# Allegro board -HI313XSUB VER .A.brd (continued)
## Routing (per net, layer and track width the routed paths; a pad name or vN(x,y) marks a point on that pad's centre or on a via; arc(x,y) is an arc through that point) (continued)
3V3_MOS_T: length 14.3
  TOP w0.381: U18.3 40.74,37.74
  TOP w0.508: LB16.1 v1(49,42.51) ; v1(15.79,39.06) 15.79,39.64 15.91,39.77 R221.1
  BOTTOM w0.508: v1(40.3,41.5) 41.31,42.51 v1(49,42.51)
  vias: v1(12.82,29.38) v1(12.84,28.62) v1(40.25,26.82) v1(40.3,35.91) v1(40.3,35.15) v1(40.27,26.05)
3V3_RF: length 37.8
  TOP w0.203: 149.13,63.72 149.13,65.42 148.82,65.73 U34.23 ; U34.28 148.94,67.73
  TOP w0.254: 148.94,67.73 149.19,67.73 150.14,68.67 C169.2
  TOP w0.381: 152.81,62.17 152.66,62.32 150.52,62.32 150.12,62.73 C144.1 149.76,63.09 149.13,63.72 ; C169.2 150.2,68.05 150.4,67.86 152.45,67.86 ; 164.78,59.05 165.62,59.89 R112.2
  TOP w0.508: 152.45,67.86 153.01,67.3 153.01,62.38 152.81,62.17
  TOP w0.635: C296.1 156.98,50.74 C57.1 C195.2 153.17,52.67 154.33,53.84 154.33,59.1 152.81,60.63 152.81,62.17
3V3_TUNER: length 88
  TOP w0.254: U20.11 24.84,59.92 23.43,58.51 ; 31.98,62.39 31.34,62.39 31,62.05 C280.2 30.65,61.69 29.88,60.92 U20.22 ; U20.15 26.97,58.01 25.82,56.86 C291.1 25.34,56.64 25.16,56.46 25.16,55.59
  TOP w0.381: 23.43,58.51 23,58.51 C286.1 22.54,58.41 22.14,58.01 22.14,54.96 22.52,54.58 25.06,54.58 25.16,54.48 ; 25.16,54.48 25.54,54.1 R213.1 26.72,52.56 27.27,52.01 v1(27.27,51.36) R225.1 ; 25.16,54.48 25.16,55.59 ; C260.1 42.57,52.78 42.84,53.05 42.84,68.8 40.93,70.71 37.63,70.71 32.78,65.86 32.78,63.06 32.11,62.39 31.98,62.39
  TOP w0.508: v1(33.05,51.99) 34.77,50.26 40.93,50.26 41.62,50.95 C260.1 C259.1 43.96,50.95 46.27,48.63 C328.1 46.27,46.08 47.3,45.05 LB16.2 ; R211.1 v1(29.25,51.98)
  BOTTOM w0.508: v1(33.05,51.99) 32.38,51.99 32.38,51.98 v1(29.25,51.98) 27.88,51.98 v1(27.27,51.36)
5V0_MOS_S:
  vias: v1(140.93,12.03) v1(140.95,12.82) v1(165.34,63.47) v1(165.34,62.71)
5V0_MOS_T: length 97.3
  TOP w0.508: Q12.2 v1(48.93,60.04)
  TOP w0.762: Q12.2 48.73,63.42 R200.1 ; v1(11.24,30.82) v1(11.24,29.99) 11.62,29.61 C352.1 11.62,26.38 14.21,23.79 49.75,23.79 52.76,26.8 52.76,29.32 52.77,29.33 v1(52.77,60.04)
  BOTTOM w0.508: v1(48.93,60.04) C301.1 v1(52.77,60.04)
  BOTTOM w0.762: v1(11.24,29.99) v1(11.24,30.82) 11.24,34.07 10.54,34.77 J4.3
12V0_MOS_S: length 11.5
  TOP w0.152: R121.1 164.81,19.61
  TOP w0.381: v1(164.81,20.39) 164.81,19.61 164.8,19.61 R117.1
  BOTTOM w0.381: v1(157.06,15.76) 159.61,15.76 164.24,20.39 v1(164.81,20.39)
GND: length 688.5
  TOP w0.152: M1.5 M4.1 ; M5.5 M3.1
  TOP w0.203: U5.9 93.53,37.07 v1(93.75,36.86) 93.56,36.67 U5.8 ; v1(92.44,39.15) 92.08,38.79 U5.11 ; 139.77,39.35 139.77,39.35 U2.34 ; v1(89.9,39.76) 90.08,39.58 U5.16 ; 22.14,39.36 22.13,39.37 U25.34 ; v1(93.65,35.71) 93.5,35.87 U5.6 ; U2.47 139.37,35.64 v1(139.9,36.17) ; 141.81,39.35 141.77,39.38 U2.29 ; v1(89.14,38.99) 89.28,38.85 U5.18 ; v1(93.71,37.62) 93.26,37.62 93.11,37.47 U5.10 ; U25.29 24.13,39.05
  TOP w0.254: U4.5 87.77,64.56 ; D3.1 v1(95.31,67.08) ; C290.2 25.82,57.63 26.47,58.27 U20.14 26.47,59.52 ; 86.6,61.64 86.42,61.64 86.01,61.24 U4.16 ; U4.18 86.77,61.58 ; 89.47,64.41 89.47,64.66 89.77,64.97 U4.1 90.29,65.49 v1(90.36,65.55) ; U4.22 88.77,61.48 ; C18.2 v1(91.42,42.07) ; U4.29 89.6,63.24 ; 86.51,63.74 U4.11
  TOP w0.305: C16.2 89.77,30.08 v1(89.63,29.94) ; C72.2 v1(84.49,40.95) ; v1(86.47,58.57) 86.47,58.34 86.77,58.03 C82.2 ; C21.2 v1(84.56,35.84) ; C26.2 89.9,42.02 v1(89.85,42.07) ; C23.2 84.69,36.86 v1(84.56,36.73) ; C17.2 94.34,36 94.05,35.71 v1(93.65,35.71) ; C32.2 v1(95.69,36.18) ; C53.2 v1(90.91,29.98)
  TOP w0.356: v1(91.38,62.07) 91.68,61.77 91.68,60.83 v1(91.78,60.72)
  TOP w0.381: C311.2 18.15,40.18 v1(18.5,39.82) ; 120.32,24.99 J5.4 ; J5.4 121.51,26.18 ; J5.4 121.51,23.79 ; J5.4 122.71,24.99 ; J7.2 63.96,33.42 ; J7.2 65.15,32.23 ; J7.2 63.96,31.03 ; J7.2 62.76,32.23 ; 23.4,80.05 J2.4 ; J2.4 26.37,81.37 ; J2.4 23.4,82.69 ; J2.4 20.43,81.37 ; J4.20 7.71,55.09 ; J4.20 6.52,56.28 ; J4.20 5.32,55.09 ; J4.20 6.52,53.89 ; J3.20 121.39,56.28 ; J3.20 120.2,55.09 ; J3.20 121.39,53.89 ; J3.20 122.59,55.09 ; C287.2 147.57,80.64 147.57,81.17 ; C287.2 147.58,81.17 ; C287.2 148.1,80.64 ; 148.73,72.4 C305.1 149.8,72.4 ; C304.1 146.76,75.15 146.76,75.68 ; C304.1 146.75,75.68 ; C304.1 146.22,75.15 ; 5.32,34.77 J4.4 ; J4.4 6.52,35.96 ; J4.4 7.71,34.77 ; J4.4 6.52,33.57 ; 144.42,79.22 C166.2 ; 144.42,79.22 144.95,79.22 ; 144.42,79.22 144.42,78.68 ; C166.2 144.42,79.75 ; C166.2 144.95,79.25 ; C286.2 v1(23.71,57.6) ; C156.2 30.19,28.57 ; C156.2 27.55,28.57 ; C156.2 28.87,27.53 ; 121.51,21.25 J5.2 ; J5.2 122.71,22.45 ; J5.2 120.32,22.45 ; J5.2 121.51,23.64 ; J16.4 139.55,81.39 ; J16.4 133.61,81.39 ; J16.4 136.58,80.07 ; J16.4 136.58,82.71 ; 64.09,23.79 J6.4 ; J6.4 62.9,24.99 ; J6.4 64.09,26.18 ; J6.4 65.28,24.99 ; 98.86,57.27 J1.7 ; J1.7 100.19,55.18 ; J1.7 100.19,59.35 ; J1.7 101.51,57.27 ; 5.32,39.85 J4.8 ; J4.8 6.52,38.65 ; J4.8 7.71,39.85 ; J4.8 6.52,41.04 ; 122.86,22.45 J5.1 ; J5.1 124.05,21.25 ; J5.1 124.05,23.64 ; J1.8 101.51,75.77 ; J1.8 98.97,75.77 ; J1.8 100.19,77.85 ; J1.8 100.19,73.68 ; J16.7 159.07,57.27 ; J16.7 157.75,55.18 ; J16.7 157.75,59.35 ; J16.7 156.43,57.27 ; 65.44,24.99 J6.3 ; J6.3 67.82,24.99 ; J6.3 66.63,26.18 ; J6.3 66.63,23.79 ; J1.6 74.16,57.27 ; J1.6 72.84,59.35 ; J1.6 71.51,57.27 ; J1.6 72.84,55.18 ; J4.18 7.71,52.55 ; J4.18 5.32,52.55 ; J4.18 6.52,51.35 ; J4.18 6.52,53.74 ; J6.2 64.09,23.64 ; J6.2 64.09,21.25 ; J6.2 65.28,22.45 ; J6.2 62.9,22.45 ; 145.21,73.27 C148.2 ; C148.2 144.15,73.27 ; C148.2 144.68,73.81 ; 7.86,39.85 J4.7 ; J4.7 9.06,38.65 ; J4.7 9.06,41.04 ; J1.4 79.01,82.71 ; J1.4 81.98,81.39 ; J1.4 79.01,80.07 ; J1.4 76.04,81.39 ; 157.75,73.68 J16.8 157.75,77.85 ; v1(16.52,39.31) 16.78,39.31 R209.2 ; 63.96,33.57 J7.4 ; J7.4 63.96,35.96 ; J7.4 62.76,34.77 ; J7.4 65.15,34.77 ; 154.38,70.45 C78.2 ; 62.76,55.09 J7.20 ; J7.20 63.96,56.28 ; J7.20 65.15,55.09 ; J7.20 63.96,53.89 ; 44.58,73.67 J2.8 ; J2.8 43.25,75.75 ; J2.8 45.9,75.75 ; J2.8 44.58,77.84 ; 63.96,36.11 J7.6 ; J7.6 63.96,38.5 ; J7.6 62.76,37.31 ; J7.6 65.15,37.31 ; J2.3 41.37,81.37 ; J2.3 35.43,81.37 ; J2.3 38.4,82.69 ; 62.76,52.55 J7.18 ; J7.18 63.96,51.35 ; J7.18 65.15,52.55 ; J7.18 63.96,53.74 ; C298.2 v1(16.55,34.94) ; C295.2 16.35,37.53 v1(16.09,37.79) ; 161.74,16.22 R102.1 ; J16.3 151.58,82.71 ; J16.3 148.61,81.39 ; J16.3 154.55,81.39 ; 7.99,22.45 J15.1 ; J15.1 9.18,23.64 ; J15.1 10.38,22.45 ; J15.1 9.18,21.25 ; v1(133.94,36.26) 134.43,35.78 C176.2 ; C545.2 v1(140.46,69.31) ; J15.4 6.64,26.18 ; J15.4 5.45,24.99 ; J15.4 6.64,23.79 ; J15.4 7.84,24.99 ; 155.67,67.51 C104.2 155.14,68.04 ; 6.64,21.25 J15.2 ; J15.2 7.84,22.45 ; J15.2 5.45,22.45 ; J15.2 6.64,23.64 ; 146.43,81.17 C288.2 145.89,80.64 ; R4.2 147.1,33.65 v1(146.95,33.5) ; 148.49,71.27 148.49,70.73 C130.2 ; C328.2 48.81,49.51 ; C328.2 47.68,48.19 ; C328.2 48.81,46.87 ; 7.99,24.99 J15.3 ; J15.3 9.18,26.18 ; J15.3 10.38,24.99 ; J15.3 9.18,23.79 ; C174.2 v1(148.9,38.5) ; 124.05,23.79 J5.3 122.86,24.99 ; C217.2 134.17,40.81 v1(133.89,40.53) ; C136.2 v1(157.87,14.59) ; J6.1 67.82,22.45 ; J6.1 65.44,22.45 ; J6.1 66.63,21.25 ; J6.1 66.63,23.64 ; J4.6 6.52,38.5 ; J4.6 5.32,37.31 ; J4.6 7.71,37.31 ; J4.6 6.52,36.11 ; C33.2 v1(85.15,68.04) ; J2.6 17.23,59.34 ; J2.6 18.55,57.25 ; J2.6 17.23,55.17 ; C535.2 v1(141.1,66.26) C241.2 ; L16.1 139.59,73.44 ; L16.1 139.05,72.92 ; L16.1 140.12,72.92 ; 130.4,73.68 J16.5 ; J16.5 130.4,77.85 ; J16.5 131.72,75.77 ; J16.5 129.08,75.77 ; v1(20.11,42.13) 19.42,42.13 R208.2 ; v1(32.55,61.89) 32.35,61.69 C280.1 ; v1(146.97,36.98) 147.13,36.82 C38.2 R83.2 ; 65.3,39.85 J7.7 66.5,38.65 ; C172.2 v1(149,41.17) ; C221.2 v1(133.94,38.75) ; J2.5 17.23,77.84 ; J2.5 17.23,73.67 ; J2.5 15.9,75.75 ; J2.5 18.55,75.75 ; v1(91.78,60.72) 91.78,60.56 92.2,60.14 v1(92.3,60.14) 92.57,60.14 92.66,60.05 93.57,60.05 v1(93.66,59.96) ; J4.2 6.52,33.42 ; J4.2 6.52,31.03 ; J4.2 7.71,32.23 ; J4.2 5.32,32.23 ; 155.14,66.51 C58.2 ; C58.2 155.67,65.98 ; C58.2 155.67,67.05 ; C226.2 v1(147.07,42.49) ; J3.18 122.59,52.55 ; J3.18 121.39,53.74 ; J3.18 120.2,52.55 ; J3.18 121.39,51.35 ; v1(133.94,42.21) 134.35,42.21 R41.2 ; J7.8 65.15,39.85 ; J7.8 63.96,38.65 ; J7.8 62.76,39.85 ; J7.8 63.96,41.04 ; C5.2 v1(85.22,67.08) ; J1.5 72.84,77.85 ; J1.5 74.16,75.77 ; J1.5 72.84,73.68 ; J1.5 71.51,75.77 ; C291.2 v1(25.82,55.09) ; J2.7 45.9,57.25 ; J2.7 44.58,55.17 ; J2.7 44.58,59.34 ; 94.01,80.07 J1.3 ; J1.3 96.98,81.39 ; J1.3 91.04,81.39 ; J1.3 94.01,82.71 ; C163.1 v1(158.94,14.62) ; C293.1 v1(24.52,63.6) ; v1(152.49,68.67) C169.1 151.6,69.36 ; 149.02,70.73 C130.2 ; C130.2 148.5,71.27 ; C534.2 v1(140.46,60.29) ; C22.2 94.6,31.95 ; C538.2 v1(140.46,61.56) ; v1(152.32,67.02) C487.1 ; C536.2 v1(140.46,68.29) ; 129.08,57.27 J16.6 130.4,59.35 ; C253.2 v1(26.73,55.85) ; C537.2 v1(140.46,64.1) ; R64.2 v1(138.2,62.83) ; C34.2 v1(106.77,34.59) ; C414.2 144.68,71.82 ; C284.1 v1(30.52,59.89) ; R59.2 v1(140.46,62.83)
  TOP w0.508: R1.2 v1(104.44,34.03) ; C71.1 v1(78.4,35.83)
  TOP w0.533: 104.78,49.09 C60.2 ; C60.2 105.83,50.34 ; C60.2 106.89,49.09 ; C60.2 105.83,47.85 ; C296.2 158.17,48.06 ; C296.2 159.42,47.01 ; C296.2 158.17,45.95 ; C296.2 156.93,47.01 ; 146.46,21.67 C134.2 ; C134.2 146.46,23.78 ; C134.2 147.71,22.73 ; C134.2 145.22,22.73 ; C4.2 109.49,30.32 ; C4.2 108.52,31.57 ; C4.2 108.52,29.08 ; 131.65,57.27 J16.6 130.4,55.26
  BOTTOM w0.152: 12.61,26.05 12.41,26.05 12.33,25.98
  BOTTOM w0.381: 65.44,24.99 J6.3 ; J6.3 66.63,23.79 ; J6.3 67.82,24.99 ; J6.3 66.63,26.18 ; J6.2 65.28,22.45 ; J6.2 62.9,22.45 ; J6.2 64.09,21.25 ; J6.2 64.09,23.64 ; 121.39,51.35 J3.18 ; J3.18 121.39,53.74 ; J3.18 120.2,52.55 ; J3.18 122.59,52.55 ; J5.3 124.05,26.18 ; J5.3 124.05,23.79 ; J5.3 122.86,24.99 ; J5.3 125.25,24.99 ; J7.7 66.5,41.04 ; J7.7 65.3,39.85 ; J7.7 66.5,38.65 ; J7.7 67.69,39.85 ; 62.76,39.85 J7.8 ; J7.8 63.96,38.65 ; J7.8 63.96,41.04 ; J7.8 65.15,39.85 ; J5.4 122.71,24.99 ; J5.4 121.51,26.18 ; J5.4 121.51,23.79 ; J5.4 120.32,24.99 ; 6.52,53.89 J4.20 ; J4.20 7.71,55.09 ; J4.20 6.52,56.28 ; J4.20 5.32,55.09 ; J6.4 65.28,24.99 ; J6.4 62.9,24.99 ; J6.4 64.09,23.79 ; J6.4 64.09,26.18 ; 38.4,80.05 J2.3 ; J2.3 38.4,82.69 ; J2.3 35.43,81.37 ; J2.3 41.37,81.37 ; J15.2 6.64,23.64 ; J15.2 6.64,21.25 ; J15.2 5.45,22.45 ; J15.2 7.84,22.45 ; 120.2,34.77 J3.4 ; J3.4 122.59,34.77 ; J3.4 121.39,33.57 ; J3.4 121.39,35.96 ; 63.96,33.57 J7.4 ; J7.4 63.96,35.96 ; J7.4 62.76,34.77 ; J7.4 65.15,34.77 ; 9.06,38.65 J4.7 ; J4.7 7.86,39.85 ; J4.7 10.25,39.85 ; J4.7 9.06,41.04 ; C328.2 48.81,49.51 ; C328.2 49.94,48.19 ; C328.2 47.68,48.19 ; C328.2 48.81,46.87 ; 121.39,36.11 J3.6 ; J3.6 121.39,38.5 ; J3.6 120.2,37.31 ; J3.6 122.59,37.31 ; 5.32,32.23 J4.2 ; J4.2 7.71,32.23 ; J4.2 6.52,33.42 ; J4.2 6.52,31.03 ; J2.4 26.37,81.37 ; J2.4 23.4,82.69 ; J2.4 23.4,80.05 ; J2.4 20.43,81.37 ; J16.4 136.58,82.71 ; J16.4 133.61,81.39 ; J16.4 139.55,81.39 ; J16.4 136.58,80.07 ; J1.4 81.98,81.39 ; J1.4 79.01,80.07 ; J1.4 76.04,81.39 ; J1.4 79.01,82.71 ; J2.8 45.9,75.75 ; J2.8 44.58,73.67 ; J2.8 43.25,75.75 ; J2.8 44.58,77.84 ; 120.2,55.09 J3.20 ; J3.20 121.39,53.89 ; J3.20 122.59,55.09 ; J3.20 121.39,56.28 ; 121.39,38.65 J3.8 ; J3.8 120.2,39.85 ; J3.8 121.39,41.04 ; J3.8 122.59,39.85 ; J2.6 17.23,59.34 ; J2.6 18.55,57.25 ; J2.6 15.9,57.25 ; J2.6 17.23,55.17 ; 123.93,38.65 J3.7 ; J3.7 123.93,41.04 ; J3.7 125.13,39.85 ; J3.7 122.74,39.85 ; v1(30.52,59.89) 29.92,59.89 29.82,59.78 v1(28.11,59.78) ; J16.3 154.55,81.39 ; J16.3 151.58,82.71 ; J16.3 148.61,81.39 ; J16.3 151.58,80.07 ; 6.52,36.11 J4.6 ; J4.6 6.52,38.5 ; J4.6 5.32,37.31 ; J4.6 7.71,37.31 ; J7.2 65.15,32.23 ; J7.2 63.96,31.03 ; J7.2 62.76,32.23 ; J7.2 63.96,33.42 ; J5.1 125.25,22.45 ; J5.1 122.86,22.45 ; J5.1 124.05,21.25 ; J5.1 124.05,23.64 ; J15.4 7.84,24.99 ; J15.4 5.45,24.99 ; J15.4 6.64,26.18 ; J15.4 6.64,23.79 ; J6.1 67.82,22.45 ; J6.1 65.44,22.45 ; J6.1 66.63,21.25 ; J6.1 66.63,23.64 ; J4.18 6.52,53.74 ; J4.18 6.52,51.35 ; J4.18 7.71,52.55 ; J4.18 5.32,52.55 ; C74.2 v1(143.21,31.03) ; 44.58,55.17 J2.7 ; J2.7 43.25,57.25 ; J2.7 45.9,57.25 ; J2.7 44.58,59.34 ; v1(26.33,61.56) 24.52,63.37 v1(24.52,63.6) ; J7.6 63.96,38.5 ; J7.6 62.76,37.31 ; J7.6 63.96,36.11 ; J7.6 65.15,37.31 ; J15.3 10.38,24.99 ; J15.3 7.99,24.99 ; J15.3 9.18,26.18 ; J15.3 9.18,23.79 ; J15.1 9.18,23.64 ; J15.1 10.38,22.45 ; J15.1 7.99,22.45 ; J15.1 9.18,21.25 ; 6.52,33.57 J4.4 ; J4.4 5.32,34.77 ; J4.4 6.52,35.96 ; J4.4 7.71,34.77 ; 120.2,32.23 J3.2 ; J3.2 122.59,32.23 ; J3.2 121.39,33.42 ; J3.2 121.39,31.03 ; 65.15,52.55 J7.18 62.76,52.55 ; J2.5 17.23,77.84 ; J2.5 17.23,73.67 ; J2.5 18.55,75.75 ; J2.5 15.9,75.75 ; 120.32,22.45 J5.2 ; J5.2 121.51,23.64 ; J5.2 122.71,22.45 ; J5.2 121.51,21.25 ; 91.04,81.39 J1.3 ; J1.3 94.01,82.71 ; J1.3 94.01,80.07 ; J1.3 96.98,81.39 ; 27.55,28.57 C156.2 ; 6.52,38.65 J4.8 ; J4.8 7.71,39.85 ; J4.8 5.32,39.85 ; J4.8 6.52,41.04 ; J7.20 65.15,55.09 ; J7.20 63.96,56.28 ; J7.20 62.76,55.09
  BOTTOM w0.533: J16.5 130.4,77.77 ; J16.5 130.4,73.76 ; J16.5 131.65,75.77 ; J16.5 129.16,75.77 ; 157.75,73.76 J16.8 ; J16.8 159,75.77 ; J16.8 156.51,75.77 ; J16.8 157.75,77.77 ; C296.2 159.42,47.01 ; C296.2 156.93,47.01 ; C296.2 158.17,48.06 ; 157.75,55.26 J16.7 ; J16.7 157.75,59.27 ; J16.7 156.51,57.27 ; J16.7 159,57.27 ; J1.5 72.84,77.77 ; J1.5 72.84,73.76 ; J1.5 71.59,75.77 ; J1.5 74.08,75.77 ; 100.19,73.76 J1.8 ; J1.8 98.94,75.77 ; J1.8 101.43,75.77 ; J1.8 100.19,77.77 ; 130.4,55.26 J16.6 ; J16.6 131.65,57.27 ; J16.6 130.4,59.27 ; J16.6 129.16,57.27 ; 108.52,29.08 C4.2 ; C4.2 108.52,31.57 ; C4.2 109.49,30.32 ; J1.7 101.43,57.27 ; J1.7 100.19,59.27 ; J1.7 98.94,57.27 ; J1.7 100.19,55.26 ; 105.83,47.85 C60.2 ; C60.2 104.78,49.09 ; C60.2 105.83,50.34 ; C60.2 106.89,49.09 ; J1.6 72.84,59.27 ; J1.6 71.59,57.27 ; J1.6 72.84,55.26 ; J1.6 74.08,57.27 ; 145.22,22.73 C134.2 ; C134.2 146.46,21.67 ; C134.2 146.46,23.78 ; C134.2 147.71,22.73
  vias: v1(0.9,75.76) v1(0.9,74.44) v1(0.9,73.17) v1(0.9,71.9) v1(0.9,70.63) v1(0.9,69.36) v1(0.9,68.09) v1(0.9,66.82) v1(0.9,65.55) v1(0.9,64.28) v1(0.9,63.01) v1(0.9,61.74) v1(0.9,60.47) v1(0.9,59.2) v1(0.9,57.93) v1(0.9,56.66) v1(0.9,55.39) v1(0.88,53.64) v1(0.88,52.37) v1(0.88,51.1) v1(0.88,49.83) v1(0.88,48.56) v1(0.88,47.29) v1(0.88,46.02) v1(0.88,44.75) v1(0.88,43.48) v1(0.88,42.21) v1(0.88,40.94) v1(0.88,39.67) v1(0.88,38.4) v1(0.88,37.13) v1(0.88,35.86) v1(0.88,34.59) v1(0.88,33.14) v1(0.88,31.87) v1(0.85,30.12) v1(0.85,28.85) v1(0.85,27.58) v1(0.85,26.31) v1(0.85,25.04) v1(0.85,23.77) v1(0.85,22.5) v1(0.85,21.23) v1(0.85,19.96) v1(0.85,18.69) v1(0.85,17.42) v1(0.85,16.15) v1(1.04,82.19) v1(0.99,10.41) v1(1.82,74.06) v1(1.82,72.41) v1(1.84,70.96) v1(1.82,69.49) v1(1.84,68.04) v1(1.82,66.44) v1(1.84,64.99) v1(1.82,58.95) v1(1.82,57.3) v1(1.84,55.85) v1(1.82,54.37) v1(1.84,52.93) v1(1.82,51.33) v1(1.84,49.88) v1(1.82,44.09) v1(1.82,42.44) v1(1.84,40.99) v1(1.82,39.52) v1(1.84,38.07) v1(1.82,36.47) v1(1.84,35.02) v1(1.93,83.18) v1(1.92,63.49) v1(1.94,62.05) v1(1.92,48.38) v1(1.94,46.93) v1(1.92,33.52) v1(1.94,32.07) v1(1.94,29.23) v1(1.94,27.58) v1(1.94,24.66) v1(1.94,21.61) v1(1.99,60.65) v1(1.99,45.54) v1(1.99,30.68) v1(1.97,26.13) v1(1.97,23.21) v1(1.97,20.16) v1(2.05,18.66) v1(1.98,9.21) v1(2.07,17.21) v1(2.59,74.82) v1(2.96,73.3) v1(2.99,71.85) v1(2.96,70.38) v1(2.99,68.93) v1(2.96,67.33) v1(2.99,65.88) v1(3.06,64.38) v1(3.09,62.93) v1(3.14,61.54) v1(3.09,59.96) v1(3.09,58.31) v1(3.11,56.86) v1(3.09,55.39) v1(3.11,53.94) v1(3.09,52.34) v1(3.11,50.89) v1(3.19,49.4) v1(3.21,47.95) v1(3.21,45.1) v1(3.21,43.45) v1(3.24,42) v1(3.21,40.53) v1(3.24,39.08) v1(3.21,37.48) v1(3.24,36.04) v1(3.26,46.55) v1(3.32,34.54) v1(3.34,33.09) v1(3.34,30.12) v1(3.34,28.47) v1(3.34,25.55) v1(3.34,22.5) v1(3.39,31.69) v1(3.37,27.02) v1(3.37,24.1) v1(3.37,21.05) v1(3.44,19.55) v1(3.47,18.1) v1(4.1,71.14) v1(4.1,69.49) v1(4.13,68.04) v1(4.1,66.57) v1(4.13,65.12) v1(4.1,63.52) v1(4.13,62.07) v1(4.2,60.57) v1(4.23,59.12) v1(4.23,56.15) v1(4.23,54.5) v1(4.23,51.58) v1(4.23,48.53) v1(4.28,72.84) v1(4.28,57.73) v1(4.26,53.05) v1(4.26,50.13) v1(4.26,47.08) v1(4.33,45.59) v1(4.29,41.47) v1(4.34,22.47) v1(4.36,44.14) v1(4.41,42.74) v1(4.52,24.56) v1(4.55,20.41) v1(4.7,28.03) v1(4.66,26.61) v1(5.03,74.77) v1(5.04,17.85) v1(5.07,19.32) v1(5.37,73.55) v1(5.37,71.9) v1(5.4,70.45) v1(5.37,68.98) v1(5.4,67.53) v1(5.37,65.93) v1(5.4,64.48) v1(5.47,62.99) v1(5.5,61.54) v1(5.59,30.45) v1(5.97,26.64) v1(6.4,20.54) v1(6.44,17.85) v1(6.47,19.32) v1(6.77,69.87) v1(6.8,68.42) v1(6.77,66.82) v1(6.8,65.37) v1(6.87,63.87) v1(6.9,62.43) v1(7.95,75.96) v1(8,9.24) v1(8.13,30.45) v1(8.12,19.32) v1(8.09,17.85) v1(8.09,16.33) v1(8.23,83.23) v1(8.17,74.44) v1(8.17,69.87) v1(8.19,68.42) v1(8.17,66.82) v1(8.19,65.37) v1(8.27,63.87) v1(8.29,62.43) v1(8.26,26.64) v1(8.43,20.47) v1(8.6,29.15) v1(9.39,19.32) v1(9.36,17.85) v1(9.36,16.33) v1(9.44,14.88) v1(9.51,82) v1(9.46,13.43) v1(9.54,11.93) v1(9.56,10.48) v1(9.64,9.26) v1(9.74,80.71) v1(9.72,79.24) v1(9.74,77.79) v1(9.74,75.89) v1(9.82,74.31) v1(9.82,69.74) v1(9.84,68.29) v1(9.82,66.69) v1(9.84,65.25) v1(9.87,83.22) v1(9.92,63.75) v1(9.95,62.3) v1(9.92,26.13) v1(9.97,30.45) v1(9.96,20.54) v1(10.41,61.31) v1(10.54,54.83) v1(10.79,52.04) v1(10.91,82) v1(11.14,80.71) v1(11.11,79.24) v1(11.14,77.79) v1(11.22,22.5) v1(11.22,20.85) v1(11.24,19.4) v1(11.22,17.93) v1(11.24,16.48) v1(11.22,14.88) v1(11.26,83.22) v1(11.27,76.4) v1(11.34,74.31) v1(11.34,72.66) v1(11.34,69.74) v1(11.34,66.69) v1(11.3,24.73) v1(11.37,71.21) v1(11.37,68.29) v1(11.37,65.25) v1(11.44,63.75) v1(11.42,9.26) v1(11.47,62.3) v1(11.52,60.9) v1(11.68,48.48) v1(11.81,59.38) v1(11.94,53.56) v1(12.31,82) v1(12.32,50.51) v1(12.28,23.69) v1(12.54,80.71) v1(12.51,79.09) v1(12.49,77.49) v1(12.51,76.04) v1(12.59,74.54) v1(12.61,73.09) v1(12.64,67.53) v1(12.61,65.93) v1(12.64,64.48) v1(12.61,22.5) v1(12.61,20.85) v1(12.64,19.4) v1(12.61,17.93) v1(12.64,16.48) v1(12.61,14.88) v1(12.66,83.22) v1(12.66,71.7) v1(12.71,62.99) v1(12.74,61.54) v1(12.79,69.67) v1(12.79,60.14) v1(12.82,48.1) v1(12.82,45.79) v1(12.82,42.61) v1(12.82,38.55) v1(12.82,9.26) v1(13.31,58.57) v1(13.46,52.04) v1(13.78,82.03) v1(13.76,78.71) v1(13.76,74.9) v1(13.76,71.09) v1(13.81,69.16) v1(13.76,67.28) v1(13.76,63.47) v1(13.83,45.54) v1(13.83,42.87) v1(13.83,39.57) v1(14.01,80.74) v1(14.14,83.24) v1(14.25,57.32) v1(14.26,22.5) v1(14.26,20.85) v1(14.29,19.4) v1(14.26,17.93) v1(14.29,16.48) v1(14.26,14.88) v1(14.29,13.43) v1(14.39,33.27) v1(14.36,11.93) v1(14.39,10.48) v1(14.52,34.74) v1(14.47,9.26) v1(14.57,77.03) v1(14.64,64.03) v1(14.67,65.63) v1(14.67,62.58) v1(14.75,61.08) v1(14.73,55.85) v1(14.8,75.02) v1(14.77,73.42) v1(14.8,71.98) v1(14.77,59.63) v1(14.87,70.48) v1(14.9,69.03) v1(14.95,67.63) v1(15.03,79.98) v1(15.54,33.72) v1(15.49,32.15) v1(15.53,22.5) v1(15.53,20.85) v1(15.53,17.93) v1(15.53,14.88) v1(15.56,19.4) v1(15.56,16.48) v1(15.56,13.43) v1(15.63,11.93) v1(15.71,63.7) v1(15.66,10.48) v1(15.74,9.26) v1(15.82,82) v1(15.84,78.81) v1(15.84,70.05) v1(15.84,67.13) v1(15.79,45.05) v1(15.94,77.59) v1(15.94,26.51) v1(15.96,73.22) v1(16.04,71.09) v1(16.04,66.01) v1(16.04,62.2) v1(16.04,59.66) v1(16.04,50.77) v1(15.96,27.73) v1(16.18,83.22) v1(16.22,53.41) v1(16.17,48.86) v1(16.17,46.96) v1(16.3,79.98) v1(16.32,68.57) v1(16.3,64.74) v1(16.42,80.87) v1(16.42,31.24) v1(16.6,69.28) v1(16.8,22.5) v1(16.8,20.85) v1(16.83,19.4) v1(16.8,17.93) v1(16.83,16.48) v1(16.8,14.88) v1(16.83,13.43) v1(16.9,11.93) v1(16.93,10.48) v1(16.98,67.25) v1(16.98,9.09) v1(17.08,71.37) v1(17.06,63.34) v1(17.06,32.07) v1(17.23,72.59) v1(17.31,79.98) v1(17.31,60.93) v1(17.49,65.35) v1(17.62,82.21) v1(17.57,52.04) v1(17.87,78.81) v1(17.87,53.41) v1(17.87,49.85) v1(18,47.95) v1(18.07,83.27) v1(18.07,66.26) v1(18.07,22.5) v1(18.07,20.85) v1(18.1,19.4) v1(18.07,17.93) v1(18.1,16.48) v1(18.07,14.88) v1(18.1,13.43) v1(18.2,72.1) v1(18.2,69.56) v1(18.17,11.93) v1(18.2,10.48) v1(18.33,46.83) v1(18.25,9.09) v1(18.38,50.74) v1(18.45,59.66) v1(18.45,54.58) v1(18.5,26.36) v1(18.58,80.74) v1(18.58,68.04) v1(18.58,64.74) v1(18.58,62.2) v1(18.59,27.76) v1(18.89,82.21) v1(19.09,63.34) v1(19.22,79.72) v1(19.34,22.5) v1(19.34,20.85) v1(19.34,17.93) v1(19.34,14.88) v1(19.37,19.4) v1(19.37,16.48) v1(19.37,13.43) v1(19.44,11.93) v1(19.47,83.27) v1(19.47,78.45) v1(19.47,70.83) v1(19.47,10.48) v1(19.52,9.09) v1(19.6,76.55) v1(19.6,74.9) v1(19.6,73.37) v1(19.6,72.23) v1(19.72,43.66) v1(19.79,68.96) v1(19.77,49.35) v1(19.85,67.28) v1(19.85,62.32) v1(19.85,48.23) v1(19.85,45.18) v1(19.98,80.74) v1(19.98,46.83) v1(20.11,64.99) v1(20.16,82.21) v1(20.61,22.5) v1(20.61,20.85) v1(20.64,19.4) v1(20.61,17.93) v1(20.64,16.48) v1(20.61,14.88) v1(20.64,13.43) v1(20.74,69.56) v1(20.71,11.93) v1(20.74,10.48) v1(20.79,9.09) v1(20.87,83.27) v1(20.92,56.61) v1(20.92,55.05) v1(20.92,54.07) v1(20.92,52.8) v1(20.99,60.29) v1(21.12,78.33) v1(21.12,77.18) v1(21.38,64.86) v1(21.5,62.96) v1(21.63,66.64) v1(21.56,27.73) v1(21.76,79.22) v1(21.88,22.5) v1(21.88,20.85) v1(21.91,19.4) v1(21.88,17.93) v1(21.91,16.48) v1(21.88,14.88) v1(21.91,13.43) v1(22.01,70.83) v1(22.01,68.29) v1(21.98,11.93) v1(22.01,10.48) v1(22.14,75.79) v1(22.06,9.09) v1(22.34,83.3) v1(22.26,46.58) v1(22.26,38.45) v1(22.26,37.18) v1(22.26,35.91) v1(22.44,53.66) v1(22.39,49.5) v1(22.39,47.85) v1(22.39,45.18) v1(22.39,43.66) v1(22.52,65.63) v1(22.57,26.36) v1(22.77,79.6) v1(22.87,69.16) v1(23.03,52.29) v1(23.15,22.5) v1(23.15,20.85) v1(23.18,19.4) v1(23.15,17.93) v1(23.18,16.48) v1(23.15,14.88) v1(23.18,13.43) v1(23.25,11.93) v1(23.28,10.48) v1(23.33,9.09) v1(23.41,67.28) v1(23.41,46.07) v1(23.53,53.69) v1(23.53,47.47) v1(23.53,38.45) v1(23.53,37.18) v1(23.53,35.91) v1(23.66,60.8) v1(23.66,48.99) v1(24.17,79.6) v1(24.3,62.48) v1(24.38,83.27) v1(24.42,71.21) v1(24.42,45.18) v1(24.42,22.5) v1(24.42,20.85) v1(24.45,19.4) v1(24.42,17.93) v1(24.45,16.48) v1(24.42,14.88) v1(24.45,13.43) v1(24.52,11.93) v1(24.55,68.29) v1(24.55,10.48) v1(24.6,9.09) v1(24.68,75.41) v1(24.68,66.13) v1(24.68,52.29) v1(24.68,48.1) v1(24.73,28.64) v1(24.8,46.58) v1(24.8,38.45) v1(24.8,37.18) v1(24.8,35.91) v1(24.93,74.14) v1(24.93,72.74) v1(24.96,50.39) v1(25.19,69.06) v1(25.24,45.41) v1(25.31,78.96) v1(25.31,76.42) v1(25.48,29.64) v1(25.69,78.07) v1(25.69,77.18) v1(25.95,75.02) v1(25.95,66.64) v1(26,49.98) v1(26.07,73.75) v1(26.12,64.26) v1(26.07,53.43) v1(26.07,48.99) v1(26.2,79.98) v1(26.2,76.17) v1(26.2,69.18) v1(26.2,68.04) v1(26.23,22.47) v1(26.23,20.82) v1(26.23,17.9) v1(26.23,14.85) v1(26.33,71.34) v1(26.33,60.67) v1(26.33,59.78) v1(26.25,19.37) v1(26.25,16.45) v1(26.25,13.4) v1(26.33,11.91) v1(26.35,83.27) v1(26.35,10.46) v1(26.4,9.06) v1(26.51,82.16) v1(26.46,78.96) v1(26.46,44.04) v1(26.51,26.36) v1(26.76,30.42) v1(26.89,28.52) v1(27.22,73.88) v1(27.22,61.56) v1(27.22,60.67) v1(27.22,59.78) v1(27.25,50.38) v1(27.39,49.09) v1(27.47,81.25) v1(27.47,79.6) v1(27.5,22.47) v1(27.5,20.82) v1(27.52,19.37) v1(27.5,17.9) v1(27.52,16.45) v1(27.5,14.85) v1(27.52,13.4) v1(27.6,11.91) v1(27.62,10.46) v1(27.75,83.27) v1(27.67,9.06) v1(27.78,82.16) v1(27.85,46.96) v1(28.11,61.56) v1(28.11,60.67) v1(28.49,57.7) v1(28.56,53.38) v1(28.74,43.53) v1(28.74,42.51) v1(28.77,22.47) v1(28.77,20.82) v1(28.79,19.37) v1(28.77,17.9) v1(28.79,16.45) v1(28.77,14.85) v1(28.79,13.4) v1(28.87,79.72) v1(28.87,11.91) v1(28.89,10.46) v1(28.94,9.06) v1(29.05,82.16) v1(29,48.1) v1(29.15,83.27) v1(29.25,45.81) v1(29.28,71.18) v1(29.29,69.06) v1(29.29,67.13) v1(29.29,64.61) v1(29.3,63.16) v1(29.27,50.9) v1(29.3,49.22) v1(29.38,75.28) v1(29.38,74.01) v1(29.38,55.72) v1(29.38,54.83) v1(29.5,76.42) v1(29.53,33.8) v1(29.63,58.51) v1(30.01,81.25) v1(30.01,79.72) v1(29.98,53.64) v1(30.03,50.01) v1(30.03,46.56) v1(30.04,22.47) v1(30.04,20.82) v1(30.04,17.9) v1(30.04,14.85) v1(30.14,71.21) v1(30.06,19.37) v1(30.06,16.45) v1(30.06,13.4) v1(30.14,11.91) v1(30.16,10.46) v1(30.21,9.06) v1(30.32,82.16) v1(30.27,75.66) v1(30.39,74.52) v1(30.39,73.37) v1(30.62,83.3) v1(30.65,78.83) v1(30.57,26.49) v1(30.9,56.36) v1(31.03,76.42) v1(31.03,57.63) v1(30.99,41.86) v1(30.95,36.39) v1(31.15,70.58) v1(31.15,69.31) v1(31.15,68.04) v1(31.15,66.77) v1(31.15,65.63) v1(31.24,55.64) v1(31.24,50.92) v1(31.2,47.59) v1(31.2,29.15) v1(31.2,27.88) v1(31.28,79.98) v1(31.28,72.87) v1(31.28,59.15) v1(31.28,54.7) v1(31.28,53.43) v1(31.28,44.42) v1(31.33,35.5) v1(31.33,33.09) v1(31.33,31.95) v1(31.31,22.47) v1(31.31,20.82) v1(31.33,19.37) v1(31.31,17.9) v1(31.33,16.45) v1(31.31,14.85) v1(31.33,13.4) v1(31.41,42.64) v1(31.41,11.91) v1(31.43,10.46) v1(31.54,74.14) v1(31.48,9.06) v1(31.59,82.16) v1(31.71,36.9) v1(31.84,41.09) v1(31.92,78.83) v1(31.92,72.1) v1(31.92,67.79) v1(32.04,45.18) v1(31.97,38.42) v1(32.17,70.83) v1(32.17,59.78) v1(32.22,35.88) v1(32.22,34.99) v1(32.3,79.72) v1(32.3,69.44) v1(32.35,42.36) v1(32.42,66.39) v1(32.55,80.61) v1(32.55,57.63) v1(32.55,56.48) v1(32.64,53.46) v1(32.55,44.16) v1(32.58,22.47) v1(32.58,20.82) v1(32.6,19.37) v1(32.58,17.9) v1(32.6,16.45) v1(32.58,14.85) v1(32.6,13.4) v1(32.66,83.27) v1(32.73,41.22) v1(32.72,34.27) v1(32.68,11.91) v1(32.7,10.46) v1(32.85,51.19) v1(32.81,45.94) v1(32.75,9.06) v1(32.86,82.16) v1(32.93,68.17) v1(33.06,60.42) v1(33.11,37.79) v1(33.11,36.01) v1(33.19,73.37) v1(33.19,70.83) v1(33.19,49.24) v1(33.31,78.83) v1(33.44,79.72) v1(33.44,71.85) v1(33.44,69.56) v1(33.41,33.83) v1(33.57,74.14) v1(33.57,46.7) v1(33.57,45.31) v1(33.57,42.77) v1(33.6,33.03) v1(33.69,54.7) v1(33.76,61.12) v1(33.82,57.75) v1(33.85,22.47) v1(33.85,20.82) v1(33.85,17.9) v1(33.85,14.85) v1(33.95,56.23) v1(33.87,41.22) v1(33.87,19.37) v1(33.87,16.45) v1(33.87,13.4) v1(33.95,11.91) v1(34,38.55) v1(33.97,10.46) v1(34.02,9.06) v1(34.13,82.16) v1(34.08,64.61) v1(34.22,32.5) v1(34.33,60.17) v1(34.48,83.3) v1(34.46,78.83) v1(34.46,76.68) v1(34.46,72.1) v1(34.46,69.56) v1(34.46,68.67) v1(34.46,63.21) v1(34.46,62.32) v1(34.58,53.43) v1(34.71,80.99) v1(34.71,79.98) v1(34.71,75.79) v1(34.71,73.37) v1(34.71,70.83) v1(34.71,65.75) v1(34.76,30.93) v1(34.76,29.66) v1(34.89,39.95) v1(35.03,32.41) v1(35.12,22.47) v1(35.12,20.82) v1(35.14,19.37) v1(35.12,17.9) v1(35.14,16.45) v1(35.12,14.85) v1(35.14,13.4) v1(35.22,11.91) v1(35.24,10.46) v1(35.35,63.98) v1(35.35,61.18) v1(35.35,56.99) v1(35.35,55.72) v1(35.29,9.06) v1(35.4,82.16) v1(35.47,51.91) v1(35.52,39.31) v1(35.6,62.07) v1(35.6,49.24) v1(35.73,73.37) v1(35.73,70.83) v1(35.73,70.07) v1(35.82,32.46) v1(35.88,83.3) v1(35.85,67.02) v1(35.98,74.64) v1(35.98,71.85) v1(35.98,65.75) v1(35.98,63.21) v1(36.03,30.42) v1(36.03,29.41) v1(36.11,76.55) v1(36.23,54.7) v1(36.36,60.29) v1(36.41,33.22) v1(36.39,22.47) v1(36.39,20.82) v1(36.41,19.37) v1(36.39,17.9) v1(36.41,16.45) v1(36.39,14.85) v1(36.41,13.4) v1(36.49,56.23) v1(36.49,46.83) v1(36.49,45.69) v1(36.49,44.67) v1(36.49,43.4) v1(36.49,42.13) v1(36.49,40.73) v1(36.49,39.46) v1(36.49,38.19) v1(36.49,36.8) v1(36.49,34.89) v1(36.49,11.91) v1(36.51,10.46) v1(36.62,57.75) v1(36.62,53.56) v1(36.56,9.06) v1(36.74,67.91) v1(36.87,79.09) v1(37,75.91) v1(37,71.85) v1(37,67.02) v1(37,63.21) v1(37,61.82) v1(37.17,30.42) v1(37.17,29.41) v1(37.27,83.3) v1(37.25,73.37) v1(37.25,65.63) v1(37.25,64.48) v1(37.25,51.91) v1(37.5,47.21) v1(37.5,46.32) v1(37.5,45.31) v1(37.5,44.04) v1(37.5,42.77) v1(37.5,41.5) v1(37.5,40.23) v1(37.5,38.96) v1(37.5,37.69) v1(37.5,36.42) v1(37.5,35.15) v1(37.63,68.67) v1(37.66,22.47) v1(37.66,20.82) v1(37.68,19.37) v1(37.66,17.9) v1(37.68,16.45) v1(37.66,14.85) v1(37.68,13.4) v1(37.76,11.91) v1(37.78,10.46) v1(37.83,9.06) v1(37.89,60.8) v1(37.89,57.75) v1(37.89,55.85) v1(37.89,54.58) v1(38.01,53.36) v1(38.01,49.24) v1(38.14,75.66) v1(38.32,30.42) v1(38.32,29.41) v1(38.39,45.81) v1(38.39,44.67) v1(38.39,43.53) v1(38.44,32.71) v1(38.44,31.82) v1(38.52,74.64) v1(38.52,71.85) v1(38.65,69.31) v1(38.65,62.32) v1(38.75,83.32) v1(38.9,41.24) v1(38.9,39.72) v1(38.9,38.19) v1(38.9,36.8) v1(38.9,35.53) v1(38.9,34.51) v1(38.93,22.47) v1(38.93,20.82) v1(38.93,17.9) v1(38.93,14.85) v1(39.03,42.64) v1(38.95,19.37) v1(38.95,16.45) v1(38.95,13.4) v1(39.03,11.91) v1(39.05,10.46) v1(39.1,9.06) v1(39.16,75.66) v1(39.54,51.91) v1(39.66,49.24) v1(39.79,79.09) v1(39.79,73.37) v1(39.79,69.31) v1(40.04,62.32) v1(40.17,76.29) v1(40.17,60.8) v1(40.17,59.28) v1(40.2,22.47) v1(40.2,20.82) v1(40.22,19.37) v1(40.2,17.9) v1(40.22,16.45) v1(40.2,14.85) v1(40.22,13.4) v1(40.3,43.27) v1(40.3,11.91) v1(40.32,10.46) v1(40.43,71.85) v1(40.37,9.06) v1(40.55,78.45) v1(40.55,53.43) v1(40.55,48.48) v1(40.68,77.31) v1(40.79,83.3) v1(40.93,68.67) v1(41.06,74.64) v1(41.06,54.32) v1(41.36,78.3) v1(41.36,76.14) v1(41.44,73.37) v1(41.44,67.79) v1(41.44,66.64) v1(41.44,65.5) v1(41.44,64.36) v1(41.44,63.09) v1(41.44,61.82) v1(41.44,60.55) v1(41.44,59.28) v1(41.44,58.01) v1(41.44,56.74) v1(41.44,55.47) v1(41.5,82.11) v1(41.49,34.23) v1(41.49,32.58) v1(41.47,22.47) v1(41.47,20.82) v1(41.49,19.37) v1(41.47,17.9) v1(41.49,16.45) v1(41.47,14.85) v1(41.49,13.4) v1(41.57,11.91) v1(41.59,10.46) v1(41.64,9.06) v1(41.87,38.68) v1(42.13,36.39) v1(42.33,71.98) v1(42.41,83.27) v1(42.38,41.47) v1(42.58,43.27) v1(42.63,32.58) v1(42.74,22.47) v1(42.74,20.82) v1(42.74,17.9) v1(42.74,14.85) v1(42.77,82.11) v1(42.79,49.24) v1(42.76,19.37) v1(42.76,16.45) v1(42.76,13.4) v1(42.84,11.91) v1(42.86,10.46) v1(42.86,9.21) v1(42.97,69.69) v1(43.02,34.36) v1(43.14,77.54) v1(43.36,80.26) v1(43.47,78.33) v1(43.52,71.19) v1(43.47,48.1) v1(43.6,66.01) v1(43.6,63.34) v1(43.6,60.67) v1(43.6,54.2) v1(43.66,67.86) v1(43.7,49.22) v1(43.73,47.08) v1(43.73,45.56) v1(43.8,83.27) v1(43.78,32.71) v1(43.9,41.47) v1(43.9,36.14) v1(44.04,82.11) v1(44.01,22.47) v1(44.01,20.82) v1(44.03,19.37) v1(44.01,17.9) v1(44.03,16.45) v1(44.01,14.85) v1(44.03,13.4) v1(44.11,43.27) v1(44.11,11.91) v1(44.13,10.46) v1(44.13,9.21) v1(44.16,79.57) v1(44.16,31.31) v1(44.35,53.13) v1(44.29,39.31) v1(44.29,38.55) v1(44.29,37.79) v1(44.29,30.3) v1(44.36,80.74) v1(44.41,27.25) v1(44.62,49.24) v1(44.64,48.13) v1(44.62,46.45) v1(44.74,70.33) v1(44.74,62.07) v1(44.67,25.09) v1(44.87,68.17) v1(44.87,64.36) v1(44.87,54.45) v1(45.05,34.36) v1(45.05,32.45) v1(45.06,66.16) v1(45.12,50.77) v1(45.2,83.27) v1(45.17,40.84) v1(45.31,82.11) v1(45.28,22.47) v1(45.28,20.82) v1(45.3,19.37) v1(45.28,17.9) v1(45.3,16.45) v1(45.28,14.85) v1(45.3,13.4) v1(45.43,26.36) v1(45.38,11.91) v1(45.4,10.46) v1(45.4,9.21) v1(45.51,45.56) v1(45.64,79.11) v1(45.68,30.42) v1(45.81,25.09) v1(45.97,77.84) v1(46.06,80.46) v1(46.06,36.14) v1(46.19,31.44) v1(46.19,27.12) v1(46.32,60.78) v1(46.32,59.38) v1(46.28,54.78) v1(46.33,44.6) v1(46.39,70.71) v1(46.39,69.44) v1(46.39,68.17) v1(46.39,66.9) v1(46.39,65.63) v1(46.39,64.36) v1(46.39,63.09) v1(46.39,52.67) v1(46.5,74.64) v1(46.58,82.11) v1(46.57,73.22) v1(46.61,57.09) v1(46.58,10.46) v1(46.67,83.3) v1(46.7,34.36) v1(46.7,32.58) v1(46.67,9.21) v1(46.81,75.81) v1(46.8,22.35) v1(46.8,20.69) v1(46.83,19.25) v1(46.8,17.77) v1(46.83,16.33) v1(47.03,49.62) v1(46.95,24.96) v1(47.16,51.02) v1(47.16,46.45) v1(47.21,25.98) v1(47.59,54.68) v1(47.59,36.26) v1(47.66,74.64) v1(47.71,70.17) v1(47.71,68.14) v1(47.66,62.58) v1(47.66,60.04) v1(47.66,57.5) v1(47.71,56.08) v1(47.84,32.58) v1(47.92,53.94) v1(48.22,34.36) v1(48.35,73.22) v1(48.43,50.89) v1(48.48,25.47) v1(48.45,22.35) v1(48.45,20.69) v1(48.48,19.25) v1(48.45,17.77) v1(48.6,31.44) v1(48.68,58.64) v1(48.68,45.31) v1(48.77,75.33) v1(48.84,35.2) v1(48.92,52.67) v1(48.86,41.73) v1(49.15,74.06) v1(49.15,45.92) v1(49.33,38.58) v1(49.44,50.51) v1(49.43,41.04) v1(49.48,36.77) v1(50.13,73.35) v1(50.38,26.1) v1(50.36,22.6) v1(50.36,20.95) v1(50.38,19.5) v1(50.36,18.03) v1(50.51,51.89) v1(50.93,74.59) v1(50.88,49.27) v1(50.88,47.21) v1(50.88,46.02) v1(50.88,43.38) v1(51.35,54.7) v1(51.64,59.07) v1(51.66,57.91) v1(51.73,53.82) v1(51.78,70.68) v1(51.78,61.16) v1(51.82,55.44) v1(51.78,27.63) v1(51.91,73.22) v1(51.89,56.58) v1(51.94,51.05) v1(51.94,49.24) v1(51.94,47.8) v1(51.94,46.2) v1(51.94,44.8) v1(51.94,43.73) v1(51.94,42.41) v1(51.92,32.48) v1(51.92,30.85) v1(51.91,29.46) v1(52.16,24.45) v1(52.26,22.6) v1(52.26,20.95) v1(52.29,19.5) v1(52.26,18.03) v1(52.36,62.45) v1(52.49,64.23) v1(52.62,69.69) v1(52.63,67.33) v1(52.67,65.35) v1(53.01,83.36) v1(53.21,75.76) v1(53.23,72.64) v1(53.16,16.73) v1(53.4,25.65) v1(53.4,23.74) v1(53.47,74.16) v1(53.47,71.37) v1(53.48,65.75) v1(53.48,62.71) v1(53.47,9.26) v1(53.56,64.33) v1(53.56,61.28) v1(53.72,49.96) v1(53.67,47.72) v1(53.67,45.51) v1(53.67,43.45) v1(53.92,68.47) v1(53.9,41.47) v1(53.99,22.5) v1(53.99,20.85) v1(54.01,19.4) v1(53.99,17.93) v1(54.31,82.14) v1(54.38,66.92) v1(54.51,77.03) v1(54.52,75.79) v1(54.52,65.63) v1(54.52,64.36) v1(54.52,63.09) v1(54.52,61.82) v1(54.52,60.55) v1(54.52,59.28) v1(54.52,58.01) v1(54.52,56.74) v1(54.52,55.47) v1(54.52,54.2) v1(54.52,52.93) v1(54.52,51.66) v1(54.52,50.39) v1(54.52,40.23) v1(54.52,38.96) v1(54.52,37.69) v1(54.52,36.42) v1(54.52,35.15) v1(54.52,33.88) v1(54.52,32.61) v1(54.52,31.34) v1(54.52,30.07) v1(54.52,28.8) v1(54.52,27.53) v1(54.52,26.26) v1(54.52,24.99) v1(54.51,16.48) v1(54.52,14.83) v1(54.51,10.64) v1(58.34,75.76) v1(58.34,65.55) v1(58.34,64.28) v1(58.34,63.01) v1(58.34,61.74) v1(58.34,60.47) v1(58.34,59.2) v1(58.34,57.93) v1(58.34,56.66) v1(58.34,55.39) v1(58.32,53.64) v1(58.32,52.37) v1(58.32,51.1) v1(58.32,49.83) v1(58.32,39.67) v1(58.32,38.4) v1(58.32,37.13) v1(58.32,35.86) v1(58.32,34.59) v1(58.32,33.14) v1(58.32,31.87) v1(58.29,30.12) v1(58.29,28.85) v1(58.29,27.58) v1(58.29,26.31) v1(58.29,25.04) v1(58.45,82.14) v1(58.42,16.43) v1(58.37,15.21) v1(58.45,10.31) v1(58.46,41.02) v1(58.57,48.34) v1(58.6,46.89) v1(58.57,45.42) v1(58.6,43.97) v1(58.57,42.37) v1(58.63,23.59) v1(58.61,21.99) v1(58.63,20.54) v1(58.71,19.04) v1(58.73,17.59) v1(58.98,73.9) v1(59,72.45) v1(58.98,70.98) v1(59,69.53) v1(58.98,67.93) v1(59.31,66.19) v1(59.28,64.99) v1(59.26,58.95) v1(59.26,57.3) v1(59.28,55.85) v1(59.26,54.37) v1(59.28,52.93) v1(59.26,51.33) v1(59.28,49.88) v1(59.31,40.76) v1(59.26,39.52) v1(59.28,38.07) v1(59.26,36.47) v1(59.28,35.02) v1(59.36,63.49) v1(59.38,62.05) v1(59.43,60.65) v1(59.36,33.52) v1(59.38,32.07) v1(59.43,30.68) v1(59.38,29.23) v1(59.38,27.58) v1(59.41,26.13) v1(59.38,24.66) v1(59.54,83.23) v1(59.64,9.09) v1(59.66,44.09) v1(59.66,42.44) v1(59.69,23.23) v1(59.66,21.63) v1(59.69,20.19) v1(59.76,48.38) v1(59.84,46.7) v1(59.76,18.69) v1(59.79,17.24) v1(60.4,73.3) v1(60.42,71.85) v1(60.4,70.38) v1(60.42,68.93) v1(60.4,67.33) v1(60.42,65.88) v1(60.48,75.15) v1(60.5,64.38) v1(60.53,62.93) v1(60.53,61.13) v1(60.53,59.48) v1(60.53,56.56) v1(60.53,53.51) v1(60.55,58.03) v1(60.55,55.11) v1(60.55,52.06) v1(60.63,50.56) v1(60.65,49.12) v1(60.7,47.72) v1(60.65,46.27) v1(60.65,44.62) v1(60.68,43.17) v1(60.65,41.7) v1(60.68,39.08) v1(60.65,37.48) v1(60.68,36.04) v1(60.76,34.54) v1(60.78,33.09) v1(60.83,31.69) v1(60.78,30.12) v1(60.78,28.47) v1(60.81,27.02) v1(60.78,25.55) v1(60.81,24.1) v1(60.78,22.5) v1(60.81,21.05) v1(60.88,19.55) v1(60.91,18.1) v1(61.54,71.14) v1(61.54,69.49) v1(61.54,66.57) v1(61.54,63.52) v1(61.57,68.04) v1(61.57,65.12) v1(61.64,61.74) v1(61.59,53.23) v1(61.64,34.99) v1(61.72,72.84) v1(61.67,60.29) v1(61.72,58.9) v1(61.67,57.32) v1(61.67,55.67) v1(61.69,54.22) v1(61.73,42.64) v1(61.69,39.92) v1(61.66,38.04) v1(61.69,36.37) v1(61.74,33.42) v1(61.82,28.8) v1(61.77,27.73) v1(61.78,22.47) v1(61.87,49.75) v1(61.9,48.3) v1(61.9,46.81) v1(61.92,45.15) v1(61.92,31.69) v1(62.03,30.4) v1(61.96,24.56) v1(61.99,20.41) v1(62.1,26.61) v1(62.48,61.18) v1(62.51,19.32) v1(62.48,17.85) v1(62.81,73.55) v1(62.81,71.9) v1(62.84,70.45) v1(62.81,68.98) v1(62.84,67.53) v1(62.81,65.93) v1(62.84,64.48) v1(62.91,62.99) v1(62.86,29.15) v1(62.99,26.13) v1(63.07,30.37) v1(63.37,62.02) v1(63.39,27.6) v1(63.63,74.97) v1(63.6,20.9) v1(63.9,19.32) v1(63.88,17.85) v1(64.21,72.79) v1(64.23,71.34) v1(64.21,69.87) v1(64.23,68.42) v1(64.21,66.82) v1(64.23,65.37) v1(64.31,63.87) v1(64.53,29.2) v1(64.64,28.11) v1(64.77,62.02) v1(64.8,30.45) v1(64.94,27.07) v1(65.18,9.26) v1(65.28,83.23) v1(65.53,17.85) v1(65.53,16.33) v1(65.61,74.44) v1(65.61,72.79) v1(65.63,71.34) v1(65.61,69.87) v1(65.63,68.42) v1(65.61,66.82) v1(65.63,65.37) v1(65.56,19.32) v1(65.71,63.87) v1(65.94,20.9) v1(66.42,61.89) v1(66.6,81.96) v1(66.67,30.47) v1(66.67,27.6) v1(66.83,19.32) v1(66.8,17.85) v1(66.8,16.33) v1(66.93,83.23) v1(66.88,14.88) v1(66.9,13.43) v1(66.98,11.93) v1(67,10.48) v1(67.08,9.21) v1(67.18,80.71) v1(67.16,79.24) v1(67.18,77.79) v1(67.18,75.89) v1(67.26,74.31) v1(67.26,72.66) v1(67.28,71.21) v1(67.26,69.74) v1(67.28,68.29) v1(67.26,66.69) v1(67.28,65.25) v1(67.36,63.75) v1(67.69,53.82) v1(67.94,61.89) v1(67.94,49.37) v1(68.04,41.57) v1(68.12,81.96) v1(68.19,57.3) v1(68.27,59.77) v1(68.33,51.53) v1(68.34,50.49) v1(68.35,37.56) v1(68.45,83.23) v1(68.52,24.53) v1(68.58,80.71) v1(68.55,79.24) v1(68.58,77.79) v1(68.71,76.4) v1(68.65,20.85) v1(68.68,19.4) v1(68.65,17.93) v1(68.68,16.48) v1(68.65,14.88) v1(68.68,13.43) v1(68.78,74.31) v1(68.78,72.66) v1(68.81,71.21) v1(68.78,69.74) v1(68.81,68.29) v1(68.78,66.69) v1(68.81,65.25) v1(68.83,23.01) v1(68.75,21.81) v1(68.76,11.93) v1(68.78,10.48) v1(68.88,63.75) v1(68.91,62.3) v1(68.86,9.21) v1(68.96,48.61) v1(69.22,59.02) v1(69.47,55.97) v1(69.46,52.42) v1(69.57,53.77) v1(69.67,38.22) v1(69.69,27.58) v1(69.77,81.96) v1(69.85,47.72) v1(69.95,79.09) v1(69.92,77.49) v1(69.95,76.04) v1(69.94,49.98) v1(70,83.28) v1(69.98,80.71) v1(70.03,74.54) v1(70.05,22.93) v1(70.05,73.09) v1(70.1,71.7) v1(70.08,67.53) v1(70.05,65.93) v1(70.08,64.48) v1(70.05,20.85) v1(70.08,19.4) v1(70.05,17.93) v1(70.08,16.48) v1(70.05,14.88) v1(70.08,13.43) v1(70.23,69.67) v1(70.15,62.99) v1(70.22,60.93) v1(70.15,11.93) v1(70.18,10.48) v1(70.27,35.68) v1(70.25,9.21) v1(70.61,57.63) v1(70.55,46.02) v1(70.55,39.26) v1(70.71,27.55) v1(70.87,59.53) v1(70.87,53.93) v1(70.88,48.33) v1(70.91,26.31) v1(71.01,21.86) v1(71.19,78.71) v1(71.19,74.9) v1(71.19,71.09) v1(71.25,69.16) v1(71.19,67.28) v1(71.19,63.47) v1(71.19,32.61) v1(71.16,28.31) v1(71.3,81.96) v1(71.45,80.74) v1(71.42,50.39) v1(71.53,83.28) v1(71.72,40.2) v1(71.7,20.85) v1(71.73,19.4) v1(71.7,17.93) v1(71.73,16.48) v1(71.7,14.88) v1(71.73,13.43) v1(71.82,45.48) v1(71.82,42.89) v1(71.8,11.93) v1(71.83,10.48) v1(71.94,79.78) v1(71.94,78.25) v1(71.91,9.21) v1(72,47.06) v1(71.98,27.55) v1(72.07,65.68) v1(72.07,64.15) v1(72.07,62.63) v1(72.07,61.11) v1(72.21,73.42) v1(72.24,71.98) v1(72.21,24.91) v1(72.31,70.48) v1(72.34,69.03) v1(72.39,67.63) v1(72.52,50.8) v1(72.64,52.67) v1(72.96,79.14) v1(73.04,47.01) v1(73.04,42.18) v1(73.04,40.56) v1(73.04,34.84) v1(73.04,30.8) v1(73,19.4) v1(72.97,17.93) v1(73,16.48) v1(72.97,14.88) v1(73,13.43) v1(73.05,80.69) v1(73.08,72.66) v1(73.08,71.14) v1(73.08,69.62) v1(73.08,68.09) v1(73.08,66.57) v1(73.08,65.04) v1(73.08,63.52) v1(73.08,62) v1(73.08,60.47) v1(73.07,11.93) v1(73.1,10.48) v1(73.18,83.28) v1(73.16,51.63) v1(73.18,9.21) v1(73.27,82.03) v1(73.37,25.47) v1(73.6,55.01) v1(73.63,23.56) v1(73.83,32.07) v1(73.97,79.78) v1(73.97,78.12) v1(74.04,53.94) v1(73.96,35.86) v1(74.11,47.54) v1(74.08,45.1) v1(74.07,42.31) v1(74.07,40.54) v1(74.24,17.93) v1(74.24,14.88) v1(74.25,68.12) v1(74.25,65.83) v1(74.25,63.8) v1(74.25,61.77) v1(74.25,55.67) v1(74.27,16.48) v1(74.27,13.43) v1(74.34,11.93) v1(74.35,71.9) v1(74.35,70.38) v1(74.35,69.11) v1(74.36,29.08) v1(74.37,10.48) v1(74.42,9.09) v1(74.7,83.28) v1(74.8,50.64) v1(74.85,24.15) v1(74.97,80.92) v1(75.14,41.88) v1(75.18,53.05) v1(75.16,47.91) v1(75.15,46.07) v1(75.18,39.03) v1(75.28,82.16) v1(75.25,59.94) v1(75.37,79.14) v1(75.37,77.62) v1(75.37,75.84) v1(75.37,74.31) v1(75.37,72.79) v1(75.37,71.27) v1(75.37,69.74) v1(75.43,22.07) v1(75.54,16.48) v1(75.51,14.88) v1(75.54,13.43) v1(75.61,11.93) v1(75.64,10.48) v1(75.69,9.09) v1(75.75,66.95) v1(75.75,64.92) v1(75.75,62.88) v1(75.75,60.85) v1(75.75,58.82) v1(75.75,56.79) v1(75.78,54.53) v1(75.88,80.03) v1(76.07,51.91) v1(76.07,31.82) v1(76.22,65.86) v1(76.24,27.53) v1(76.3,83.31) v1(76.39,78.25) v1(76.39,76.73) v1(76.39,74.95) v1(76.39,73.43) v1(76.39,71.9) v1(76.39,70.38) v1(76.39,69.11) v1(76.45,63.93) v1(76.42,33.39) v1(76.5,55.57) v1(76.52,29.58) v1(76.5,22.85) v1(76.57,62.78) v1(76.62,58.13) v1(76.62,20.92) v1(76.81,16.48) v1(76.78,14.88) v1(76.81,13.43) v1(76.88,11.93) v1(76.91,10.48) v1(76.96,9.09) v1(77.15,79.9) v1(77.15,77.62) v1(77.15,61.74) v1(77.17,53.39) v1(77.18,28.47) v1(77.27,74.31) v1(77.27,71.27) v1(77.31,25.72) v1(77.4,78.63) v1(77.4,75.71) v1(77.53,76.73) v1(77.64,34.21) v1(77.83,83.31) v1(77.91,72.79) v1(78.04,62.76) v1(77.99,52.48) v1(77.96,38.06) v1(78.08,19.4) v1(78.08,16.48) v1(78.05,14.88) v1(78.08,13.43) v1(78.16,79.14) v1(78.17,36.92) v1(78.15,11.93) v1(78.18,10.48) v1(78.23,9.09) v1(78.29,75.2) v1(78.29,73.68) v1(78.29,70.63) v1(78.42,79.9) v1(78.35,20.77) v1(78.63,54.64) v1(78.58,25.72) v1(78.8,76.22) v1(78.8,61.74) v1(78.76,39.52) v1(78.81,28.09) v1(78.93,74.19) v1(78.86,71.82) v1(79.18,79.14) v1(79.16,63.8) v1(79.31,69.74) v1(79.26,52.35) v1(79.34,36.92) v1(79.35,19.4) v1(79.35,16.48) v1(79.32,14.88) v1(79.35,13.43) v1(79.43,45.18) v1(79.35,43.49) v1(79.42,11.93) v1(79.45,10.48) v1(79.48,83.31) v1(79.47,38.07) v1(79.5,9.09) v1(79.6,30.96) v1(79.69,79.9) v1(79.69,75.33) v1(79.7,60.62) v1(79.67,58.69) v1(79.8,66.85) v1(79.85,25.72) v1(79.88,23.67) v1(79.95,55.85) v1(80,32.3) v1(79.98,29.64) v1(80.03,28.11) v1(80.07,68.09) v1(80.07,65.81) v1(80.07,63.77) v1(80.07,61.74) v1(80.07,59.71) v1(80.07,57.68) v1(80.09,53.39) v1(80.12,26.59) v1(80.2,78.89) v1(80.2,73.93) v1(80.2,73.04) v1(80.2,72.03) v1(80.2,43.46) v1(80.34,49.82) v1(80.28,45.17) v1(80.41,51.34) v1(80.37,34.04) v1(80.37,24.91) v1(80.55,42.31) v1(80.55,41.08) v1(80.58,76.6) v1(80.58,74.7) v1(80.62,19.4) v1(80.62,16.48) v1(80.59,14.88) v1(80.62,13.43) v1(80.69,11.93) v1(80.72,10.48) v1(80.83,70.63) v1(80.83,69.11) v1(80.77,9.09) v1(81,83.31) v1(80.96,79.9) v1(80.96,61.74) v1(81.04,60.49) v1(81.04,58.71) v1(81.08,66.95) v1(81.07,63.75) v1(81.12,52.37) v1(81.14,38.26) v1(81.14,25.7) v1(81.24,65.45) v1(81.21,64.56) v1(81.22,43.05) v1(81.34,78.38) v1(81.34,73.04) v1(81.27,28.21) v1(81.42,56.68) v1(81.42,54.77) v1(81.4,41.5) v1(81.37,37.13) v1(81.39,34.09) v1(81.47,75.71) v1(81.47,71.52) v1(81.59,73.81) v1(81.72,61.49) v1(81.89,19.4) v1(81.89,16.48) v1(81.86,14.88) v1(81.89,13.43) v1(81.97,53.49) v1(81.98,51.31) v1(81.96,11.93) v1(81.99,10.48) v1(82.04,9.09) v1(82.1,79.9) v1(82.06,49.98) v1(82.23,72.16) v1(82.23,70.12) v1(82.18,68.49) v1(82.18,60.65) v1(82.23,58.95) v1(82.32,83.33) v1(82.35,74.95) v1(82.44,71.03) v1(82.48,77.49) v1(82.54,42.28) v1(82.61,72.92) v1(82.72,82.11) v1(82.82,69.25) v1(82.79,37.24) v1(82.77,34.08) v1(82.79,26.42) v1(82.95,28.19) v1(82.91,25.07) v1(82.99,79.14) v1(82.99,61.49) v1(82.99,54.5) v1(83.12,76.85) v1(83.12,74.19) v1(83.2,55.91) v1(83.24,53.36) v1(83.22,52.28) v1(83.25,51.19) v1(83.3,63.91) v1(83.35,31.88) v1(83.41,50.06) v1(83.41,22.24) v1(83.5,73.43) v1(83.5,70) v1(83.45,59.72) v1(83.5,57.8) v1(83.51,23.39) v1(83.61,81.35) v1(83.62,79.9) v1(83.62,76.25) v1(83.58,68.49) v1(83.62,66.31) v1(83.66,37.38) v1(83.69,19.37) v1(83.69,16.45) v1(83.67,14.85) v1(83.69,13.4) v1(83.85,83.33) v1(83.75,78.25) v1(83.75,67.58) v1(83.77,11.91) v1(83.79,10.46) v1(83.84,9.06) v1(83.88,61.49) v1(84.01,72.84) v1(84.01,54.25) v1(84.04,25.29) v1(84.12,63.9) v1(84.13,58.57) v1(84.09,56.68) v1(84.24,82.11) v1(84.21,71.41) v1(84.18,28.5) v1(84.31,33.96) v1(84.31,26.34) v1(84.44,31.85) v1(84.51,79.14) v1(84.47,69.38) v1(84.47,68.49) v1(84.47,60.74) v1(84.54,38.23) v1(84.64,77.24) v1(84.64,75.2) v1(84.6,40.07) v1(84.56,24.18) v1(84.77,72.28) v1(84.78,22.14) v1(84.94,14.85) v1(84.96,19.37) v1(84.96,16.45) v1(84.96,13.4) v1(85.04,11.91) v1(85.13,81.35) v1(85.1,53.37) v1(85.1,52.38) v1(85.11,51.2) v1(85.13,23.26) v1(85.06,10.46) v1(85.11,9.06) v1(85.28,79.9) v1(85.28,59.84) v1(85.4,71.65) v1(85.36,69.76) v1(85.4,65.42) v1(85.43,31.85) v1(85.36,24.91) v1(85.5,83.33) v1(85.51,26.46) v1(85.58,27.36) v1(85.66,74.31) v1(85.68,45.92) v1(85.71,44.88) v1(85.82,39.97) v1(85.83,38.4) v1(85.9,82.11) v1(85.91,71.01) v1(86.04,75.33) v1(85.96,33.96) v1(86.12,77.24) v1(86.05,22.14) v1(86.16,79.14) v1(86.23,19.37) v1(86.23,16.45) v1(86.21,14.85) v1(86.23,13.4) v1(86.34,28.5) v1(86.31,11.91) v1(86.33,10.46) v1(86.37,68.99) v1(86.37,52.25) v1(86.35,42.72) v1(86.38,9.06) v1(86.63,24.91) v1(86.67,73.55) v1(86.66,51.25) v1(86.68,25.85) v1(86.78,81.35) v1(86.8,79.9) v1(86.84,45.92) v1(86.88,74.58) v1(86.88,56.8) v1(86.86,45.1) v1(86.86,26.89) v1(87.02,83.33) v1(87,64) v1(87,62.99) v1(87,61.97) v1(87.03,53.69) v1(87.01,23.59) v1(87.06,30.07) v1(87.31,72.54) v1(87.32,22.14) v1(87.42,82.11) v1(87.43,69.87) v1(87.5,55.16) v1(87.5,19.37) v1(87.5,16.45) v1(87.48,14.85) v1(87.5,13.4) v1(87.56,75.33) v1(87.62,39.82) v1(87.58,11.91) v1(87.6,10.46) v1(87.69,79.14) v1(87.69,77.24) v1(87.73,57.58) v1(87.65,9.06) v1(87.77,74.2) v1(87.8,38.27) v1(87.83,30.93) v1(87.89,68.47) v1(87.89,67.2) v1(87.9,24.91) v1(88.02,64) v1(88.02,62.99) v1(88.02,61.97) v1(87.98,50.18) v1(87.95,30.12) v1(88.11,51.3) v1(88.12,27.36) v1(88.05,26.46) v1(88.15,72.3) v1(88.23,52.27) v1(88.28,55.16) v1(88.28,23.59) v1(88.44,83.31) v1(88.39,81.25) v1(88.4,42) v1(88.53,80.17) v1(88.45,57.93) v1(88.48,39.57) v1(88.63,59.57) v1(88.59,22.14) v1(88.66,71.28) v1(88.75,14.85) v1(88.79,43.12) v1(88.77,19.37) v1(88.77,16.45) v1(88.77,13.4) v1(88.85,11.91) v1(88.88,53.63) v1(88.87,10.46) v1(88.92,9.06) v1(89.02,82.01) v1(89.03,64) v1(89.03,62.99) v1(89.03,61.97) v1(89.14,36.86) v1(89.16,35.84) v1(89.16,34.7) v1(89.17,24.91) v1(89.26,28.5) v1(89.32,26.46) v1(89.42,75.6) v1(89.55,76.61) v1(89.55,23.59) v1(89.72,78.38) v1(89.67,77.44) v1(89.67,72.17) v1(89.67,70.77) v1(89.67,69.62) v1(89.67,68.6) v1(89.67,67.61) v1(89.73,49.62) v1(89.93,80.17) v1(89.86,22.14) v1(89.97,83.31) v1(89.99,81.25) v1(90.04,19.37) v1(90.04,16.45) v1(90.02,14.85) v1(90.04,13.4) v1(90.12,11.91) v1(90.14,10.46) v1(90.18,36.86) v1(90.18,35.84) v1(90.18,34.7) v1(90.19,9.06) v1(90.44,59.86) v1(90.37,53.49) v1(90.62,82.01) v1(90.69,75.6) v1(90.69,73.82) v1(90.7,27.55) v1(90.76,59.05) v1(90.79,57.91) v1(90.85,51.53) v1(90.84,48.55) v1(90.82,47.53) v1(90.82,46.13) v1(90.82,23.59) v1(91.07,80.17) v1(91.12,66.31) v1(91.08,55.16) v1(91.13,22.14) v1(91.19,36.86) v1(91.19,35.84) v1(91.19,34.7) v1(91.26,44.88) v1(91.31,19.37) v1(91.31,16.45) v1(91.29,14.85) v1(91.31,13.4) v1(91.42,56.59) v1(91.39,53.23) v1(91.39,11.91) v1(91.41,10.46) v1(91.55,59.35) v1(91.55,58.24) v1(91.55,28.61) v1(91.46,9.06) v1(91.62,83.31) v1(91.63,77.87) v1(91.63,76.85) v1(91.63,73.43) v1(91.61,46.93) v1(91.65,31.5) v1(91.75,66.95) v1(91.88,69.11) v1(92.09,75.6) v1(92.34,79.79) v1(92.32,23.62) v1(92.44,30.02) v1(92.4,22.14) v1(92.47,71.53) v1(92.46,27.84) v1(92.6,56.65) v1(92.63,52.88) v1(92.63,50.59) v1(92.58,19.37) v1(92.58,16.45) v1(92.56,14.85) v1(92.58,13.4) v1(92.66,11.91) v1(92.68,10.46) v1(92.73,9.06) v1(92.82,32.8) v1(92.9,73.43) v1(92.95,58.69) v1(92.95,26.57) v1(92.98,66.71) v1(92.98,57.56) v1(93.14,83.31) v1(93.1,69.76) v1(93.1,68.11) v1(93.2,39.53) v1(93.28,79.14) v1(93.51,56.65) v1(93.45,55.19) v1(93.54,47.54) v1(93.61,76.11) v1(93.61,74.96) v1(93.61,73.95) v1(93.71,64.69) v1(93.71,63.67) v1(93.71,62.66) v1(93.74,58.45) v1(93.71,38.66) v1(93.71,32.26) v1(93.67,22.14) v1(93.85,25.52) v1(93.83,23.62) v1(93.83,14.85) v1(93.9,45.74) v1(93.92,44.29) v1(93.95,41.09) v1(93.85,19.37) v1(93.85,16.45) v1(93.85,13.4) v1(93.93,11.91) v1(93.99,71.53) v1(93.97,42.51) v1(93.95,10.46) v1(94,9.06) v1(94.29,68.09) v1(94.3,51.5) v1(94.34,39.55) v1(94.41,83.31) v1(94.42,65.06) v1(94.42,64.15) v1(94.43,63.21) v1(94.43,54.04) v1(94.55,79.14) v1(94.5,73.44) v1(94.46,62.35) v1(94.5,59.34) v1(94.5,57.69) v1(94.53,56.65) v1(94.46,53.21) v1(94.67,48.38) v1(94.75,75.09) v1(94.94,31.08) v1(94.94,22.14) v1(94.98,38.66) v1(94.98,26.57) v1(95.14,76.49) v1(95.1,23.62) v1(95.12,19.37) v1(95.12,16.45) v1(95.1,14.85) v1(95.12,13.4) v1(95.2,11.91) v1(95.22,10.46) v1(95.34,33.57) v1(95.31,27.84) v1(95.27,9.06) v1(95.42,71.38) v1(95.39,70.01) v1(95.39,68.49) v1(95.42,50.13) v1(95.44,35.23) v1(95.55,42.84) v1(95.56,78.76) v1(95.56,75.84) v1(95.56,74.06) v1(95.6,45.08) v1(95.6,41.12) v1(95.65,29.86) v1(95.74,39.53) v1(95.74,37.75) v1(95.82,77.62) v1(95.75,32.48) v1(95.94,83.31) v1(96.2,63.14) v1(96.2,61.61) v1(96.2,60.09) v1(96.2,58.82) v1(96.2,57.3) v1(96.2,55.77) v1(96.2,54.25) v1(96.21,22.14) v1(96.28,72.42) v1(96.32,67.08) v1(96.41,71.41) v1(96.37,23.62) v1(96.39,19.37) v1(96.39,16.45) v1(96.37,14.85) v1(96.39,13.4) v1(96.45,78.25) v1(96.45,76.73) v1(96.45,75.2) v1(96.45,73.43) v1(96.45,70.12) v1(96.45,68.35) v1(96.47,48.7) v1(96.47,11.91) v1(96.49,10.46) v1(96.54,9.06) v1(96.7,46.36) v1(96.87,31.18) v1(96.92,29.86) v1(97.02,52.06) v1(97.02,32.48) v1(96.97,28.16) v1(97.09,80.28) v1(97.21,72.41) v1(97.21,70.89) v1(97.21,69.36) v1(97.21,67.84) v1(97.21,65.55) v1(97.21,62.5) v1(97.21,60.98) v1(97.21,59.71) v1(97.21,58.19) v1(97.21,56.66) v1(97.21,55.14) v1(97.21,53.49) v1(97.34,77.24) v1(97.34,75.71) v1(97.34,74.19) v1(97.4,82.19) v1(97.48,22.14) v1(97.59,83.31) v1(97.61,27.45) v1(97.64,23.62) v1(97.64,14.85) v1(97.66,19.37) v1(97.66,16.45) v1(97.66,13.4) v1(97.74,11.91) v1(97.76,36.11) v1(97.76,10.46) v1(97.81,9.06) v1(97.88,51.15) v1(97.95,44.61) v1(97.94,43.05) v1(98.04,40.73) v1(97.99,38.42) v1(98.01,28.75) v1(98.23,79.27) v1(98.23,73.04) v1(98.23,71.52) v1(98.23,70) v1(98.23,68.47) v1(98.23,66.31) v1(98.23,64.66) v1(98.23,63.14) v1(98.23,61.61) v1(98.23,60.09) v1(98.23,58.82) v1(98.23,57.3) v1(98.23,55.77) v1(98.23,54.25) v1(98.19,29.86) v1(98.32,47.16) v1(98.29,32.48) v1(98.36,74.82) v1(98.49,81.27) v1(98.74,53.49) v1(98.85,55.06) v1(98.89,26.47) v1(98.9,25.57) v1(98.91,23.62) v1(98.93,19.37) v1(98.93,16.45) v1(98.91,14.85) v1(98.93,13.4) v1(98.99,80.28) v1(98.96,24.57) v1(99.01,11.91) v1(99.03,10.46) v1(99.11,83.31) v1(99.08,9.06) v1(99.25,79.39) v1(99.25,77.87) v1(99.25,73.04) v1(99.25,71.39) v1(99.25,69.87) v1(99.25,68.35) v1(99.25,66.82) v1(99.25,65.3) v1(99.25,63.77) v1(99.25,62.25) v1(99.25,60.73) v1(99.25,59.2) v1(99.23,52.11) v1(99.26,28.72) v1(99.31,27.5) v1(99.36,31.16) v1(99.52,82.09) v1(99.46,29.86) v1(99.64,54.3) v1(99.64,38.78) v1(99.64,36.37) v1(99.61,34.13) v1(99.56,32.48) v1(99.66,42.08) v1(99.99,80.61) v1(99.98,47.28) v1(99.96,46.01) v1(99.98,44.74) v1(100.2,19.37) v1(100.2,16.45) v1(100.18,14.85) v1(100.2,13.4) v1(100.28,11.91) v1(100.3,10.46) v1(100.42,52.83) v1(100.35,9.14) v1(100.46,83.28) v1(100.48,79.24) v1(100.65,51.81) v1(101.05,82.09) v1(101.01,46.22) v1(100.96,43.4) v1(101.16,42.06) v1(101.31,44.24) v1(101.45,20.82) v1(101.45,14.85) v1(101.47,16.45) v1(101.47,13.4) v1(101.55,11.91) v1(101.59,80.49) v1(101.64,71.8) v1(101.57,10.46) v1(101.62,9.14) v1(101.69,73.2) v1(101.74,66.92) v1(101.69,65.68) v1(101.69,64.28) v1(101.69,63.01) v1(101.69,61.74) v1(101.69,60.47) v1(101.69,59.2) v1(101.69,57.93) v1(101.72,56.58) v1(101.69,55.39) v1(101.69,54.12) v1(101.69,52.85) v1(101.69,51.58) v1(101.82,69.92) v1(101.77,68.52) v1(101.98,83.28) v1(102.15,79.19) v1(102.1,77.79) v1(102.1,42.51) v1(102.18,21.71) v1(102.5,76.24) v1(102.45,74.85) v1(102.51,38.83) v1(102.63,36.42) v1(102.61,34.38) v1(102.7,82.09) v1(102.72,17.9) v1(102.74,16.45) v1(102.72,14.85) v1(102.74,13.4) v1(102.81,32.48) v1(102.84,31.03) v1(102.79,29.48) v1(102.81,28.03) v1(102.81,25.72) v1(102.84,24.28) v1(102.82,11.91) v1(102.84,10.46) v1(102.89,9.14) v1(103.24,71.67) v1(103.34,80.16) v1(103.32,77.56) v1(103.29,73.07) v1(103.34,66.8) v1(103.29,65.55) v1(103.29,64.15) v1(103.29,62.88) v1(103.29,61.61) v1(103.29,60.34) v1(103.29,59.07) v1(103.29,57.8) v1(103.29,56.53) v1(103.29,55.26) v1(103.29,53.99) v1(103.29,52.72) v1(103.29,51.45) v1(103.43,81.08) v1(103.37,78.96) v1(103.42,69.79) v1(103.37,68.4) v1(103.63,83.28) v1(103.6,41.83) v1(104.1,76.12) v1(104.05,74.72) v1(104.22,82.09) v1(104.24,17.77) v1(104.16,9.14) v1(104.27,19.25) v1(104.27,16.33) v1(104.72,32.73) v1(104.74,31.29) v1(104.69,29.74) v1(104.72,28.29) v1(104.72,25.98) v1(104.74,24.53) v1(105.04,72.74) v1(104.99,71.34) v1(105.04,65.22) v1(105.05,63.82) v1(105.05,62.55) v1(105.05,61.28) v1(105.05,60.01) v1(105.05,58.74) v1(105.05,57.47) v1(105.05,56.2) v1(105.05,54.93) v1(105.05,53.66) v1(105.05,52.39) v1(105.05,51.12) v1(105.12,68.07) v1(105.09,66.47) v1(105.16,83.28) v1(105.17,69.46) v1(105.2,46.68) v1(105.8,74.39) v1(105.89,20.69) v1(105.92,19.25) v1(105.89,17.77) v1(106.82,71.9) v1(106.87,73.3) v1(106.95,68.62) v1(106.92,67.02) v1(106.87,65.78) v1(106.88,64.38) v1(106.88,63.11) v1(106.88,61.84) v1(106.88,60.57) v1(106.88,59.3) v1(106.88,58.03) v1(106.88,56.76) v1(106.88,55.49) v1(106.88,54.22) v1(106.88,52.95) v1(106.88,51.68) v1(107,70.02) v1(107,46.68) v1(107.8,20.95) v1(107.82,19.5) v1(107.8,18.03) v1(108.02,41.93) v1(108.04,40.48) v1(108.2,24.83) v1(108.27,27.96) v1(108.3,26.51) v1(108.43,22.85) v1(108.65,72.31) v1(108.65,62.96) v1(108.62,61.36) v1(108.57,60.12) v1(108.58,58.72) v1(108.58,57.45) v1(108.58,56.18) v1(108.58,54.91) v1(108.58,53.64) v1(108.58,52.37) v1(108.58,51.1) v1(108.58,49.83) v1(108.58,48.56) v1(108.58,47.29) v1(108.58,46.02) v1(108.63,44.14) v1(108.7,73.7) v1(108.7,66.19) v1(108.7,64.36) v1(108.83,70.43) v1(108.78,69.03) v1(108.75,67.43) v1(108.78,45.05) v1(109.29,32.91) v1(109.6,24.45) v1(109.7,22.6) v1(109.92,42.18) v1(109.95,40.73) v1(110.08,21.53) v1(110.08,19.88) v1(110.08,18.43) v1(110.08,16.96) v1(110.18,28.21) v1(110.2,26.76) v1(110.33,59.4) v1(110.34,58.01) v1(110.34,56.74) v1(110.34,55.47) v1(110.34,54.2) v1(110.34,52.93) v1(110.34,51.66) v1(110.34,50.39) v1(110.34,49.12) v1(110.34,47.85) v1(110.34,46.58) v1(110.34,45.31) v1(110.34,44.04) v1(110.43,71.55) v1(110.41,62.25) v1(110.38,60.65) v1(110.43,39.06) v1(110.43,37.79) v1(110.43,36.52) v1(110.43,35.25) v1(110.43,33.98) v1(110.43,32.71) v1(110.43,31.44) v1(110.43,30.17) v1(110.51,74.57) v1(110.48,72.94) v1(110.53,66.67) v1(110.48,65.42) v1(110.46,63.65) v1(110.61,69.67) v1(110.55,68.27) v1(110.62,9.06) v1(110.84,25.65) v1(110.84,23.74) v1(110.9,83.15) v1(111.24,42.18) v1(111.27,40.73) v1(111.64,72.74) v1(111.58,71.34) v1(111.62,23.13) v1(111.62,21.48) v1(111.62,20.03) v1(111.62,18.56) v1(111.55,16.81) v1(111.67,74.36) v1(111.71,68.06) v1(111.69,66.46) v1(111.65,49.12) v1(111.65,47.85) v1(111.65,46.58) v1(111.65,45.31) v1(111.65,44.04) v1(111.76,69.46) v1(111.96,81.6) v1(112.01,76.42) v1(111.96,65.63) v1(111.96,64.36) v1(111.96,63.09) v1(111.96,61.82) v1(111.96,60.55) v1(111.96,59.28) v1(111.96,58.01) v1(111.96,56.74) v1(111.96,55.47) v1(111.96,54.2) v1(111.96,52.93) v1(111.96,51.66) v1(111.96,50.39) v1(111.96,40.23) v1(111.96,38.96) v1(111.96,37.69) v1(111.96,36.42) v1(111.96,35.15) v1(111.96,33.88) v1(111.96,32.61) v1(111.96,31.34) v1(111.96,30.07) v1(111.96,28.8) v1(111.96,27.53) v1(111.96,26.26) v1(111.96,24.99) v1(111.96,14.83) v1(111.99,10.64) v1(115.63,14.8) v1(115.83,75.81) v1(115.83,65.6) v1(115.83,64.33) v1(115.83,63.06) v1(115.83,61.79) v1(115.83,60.52) v1(115.83,59.25) v1(115.83,57.98) v1(115.83,56.71) v1(115.83,55.44) v1(115.81,53.69) v1(115.81,52.42) v1(115.81,51.15) v1(115.81,49.88) v1(115.81,39.72) v1(115.81,38.45) v1(115.81,37.18) v1(115.81,35.91) v1(115.81,34.64) v1(115.81,33.19) v1(115.81,31.92) v1(115.78,30.17) v1(115.78,28.9) v1(115.81,27.17) v1(115.81,25.72) v1(115.81,24.45) v1(115.8,10.53) v1(115.93,82.19) v1(115.92,41.13) v1(116.03,47) v1(116.01,22.69) v1(115.96,21.24) v1(116.03,19.95) v1(115.98,18.5) v1(115.98,17.1) v1(116.08,48.45) v1(116.1,45.71) v1(116.05,44.26) v1(116.05,42.86) v1(116.29,74.16) v1(116.29,72.51) v1(116.32,71.06) v1(116.29,69.58) v1(116.32,68.14) v1(116.29,66.54) v1(116.36,16.17) v1(116.75,59) v1(116.75,57.35) v1(116.75,54.43) v1(116.75,51.38) v1(116.75,39.57) v1(116.75,36.52) v1(116.77,65.04) v1(116.85,63.54) v1(116.77,55.9) v1(116.77,52.98) v1(116.77,49.93) v1(116.77,38.12) v1(116.77,35.07) v1(116.85,33.57) v1(116.78,27.6) v1(116.87,62.1) v1(116.92,60.7) v1(116.87,32.12) v1(116.92,30.73) v1(116.87,29.28) v1(116.85,26.1) v1(116.88,24.66) v1(116.99,83.23) v1(117.05,44.11) v1(117.05,42.46) v1(117.08,41.01) v1(117.11,21.76) v1(117.13,19.02) v1(117.13,17.62) v1(117.14,9.01) v1(117.15,48.41) v1(117.18,46.96) v1(117.23,45.56) v1(117.16,23.21) v1(117.18,20.47) v1(117.86,75.02) v1(117.89,73.35) v1(117.92,71.9) v1(117.89,70.43) v1(117.92,68.98) v1(117.89,67.38) v1(117.92,65.93) v1(117.99,64.43) v1(118.02,62.99) v1(118.02,60.01) v1(118.02,58.36) v1(118.04,56.91) v1(118.02,55.44) v1(118.04,53.99) v1(118.02,52.39) v1(118.04,50.95) v1(118.07,61.59) v1(118.12,49.45) v1(118.14,48) v1(118.14,45.15) v1(118.14,43.5) v1(118.14,40.58) v1(118.14,37.53) v1(118.12,28.54) v1(118.14,18.61) v1(118.19,46.6) v1(118.17,42.06) v1(118.17,39.13) v1(118.17,36.09) v1(118.25,34.59) v1(118.22,21.38) v1(118.25,17.11) v1(118.27,33.14) v1(118.32,31.74) v1(118.27,30.17) v1(118.25,27.12) v1(118.28,25.67) v1(118.33,24.28) v1(118.28,22.7) v1(118.3,19.96) v1(119.03,71.19) v1(119.03,69.54) v1(119.03,66.62) v1(119.03,63.57) v1(119.06,68.09) v1(119.06,65.17) v1(119.06,62.12) v1(119.13,60.62) v1(119.08,52.11) v1(119.13,35.05) v1(119.21,72.89) v1(119.16,59.18) v1(119.21,57.78) v1(119.16,56.2) v1(119.16,54.55) v1(119.19,53.1) v1(119.22,41.52) v1(119.18,39.97) v1(119.15,38.09) v1(119.18,36.42) v1(119.23,33.47) v1(119.24,26) v1(119.31,28.85) v1(119.31,21.38) v1(119.33,18.64) v1(119.41,50.23) v1(119.36,48.63) v1(119.39,47.19) v1(119.39,45.69) v1(119.41,44.04) v1(119.41,31.74) v1(119.41,24.28) v1(119.58,23.18) v1(119.82,17.62) v1(119.86,20.08) v1(120.02,30.65) v1(120.3,26.49) v1(120.37,74.85) v1(120.43,71.39) v1(120.43,69.74) v1(120.43,66.82) v1(120.43,63.77) v1(120.46,68.29) v1(120.46,65.37) v1(120.53,61.99) v1(120.61,73.09) v1(120.91,29.18) v1(120.91,27.73) v1(121.18,20.29) v1(121.32,19.02) v1(121.55,74.16) v1(121.47,17.62) v1(122.11,71.39) v1(122.11,69.74) v1(122.13,68.29) v1(122.11,66.82) v1(122.13,65.37) v1(122.11,63.77) v1(122.21,61.99) v1(122.28,73.09) v1(122.25,27.5) v1(122.38,83.36) v1(122.38,30.65) v1(122.58,9.24) v1(122.71,20.31) v1(122.74,17.62) v1(122.76,26.36) v1(122.94,74.36) v1(122.87,16.25) v1(122.97,19.02) v1(123.53,71.21) v1(123.53,69.56) v1(123.53,66.64) v1(123.53,63.59) v1(123.55,68.12) v1(123.55,65.2) v1(123.63,61.82) v1(123.73,82.1) v1(123.71,72.92) v1(123.78,83.34) v1(124.09,76.42) v1(124.14,16.25) v1(124.19,80.22) v1(124.18,78.4) v1(124.23,20.34) v1(124.24,19.02) v1(124.24,17.67) v1(124.21,14.8) v1(124.24,13.35) v1(124.32,11.86) v1(124.34,10.41) v1(124.42,9.19) v1(124.62,74.36) v1(125.13,71.29) v1(125.13,69.64) v1(125.13,66.72) v1(125.13,63.67) v1(125.15,68.19) v1(125.15,65.27) v1(125.15,62.22) v1(125.25,59.3) v1(125.3,83.37) v1(125.26,82.12) v1(125.31,72.99) v1(125.41,76.4) v1(125.51,80.19) v1(125.5,78.38) v1(125.6,58.26) v1(125.61,49.19) v1(125.71,14.75) v1(125.88,51.17) v1(125.91,42.89) v1(126.04,74.19) v1(126.01,61.31) v1(126.02,13.35) v1(126.09,11.86) v1(126.12,10.41) v1(126.2,40.66) v1(126.2,38.58) v1(126.2,9.19) v1(126.26,45.1) v1(126.52,35.48) v1(126.55,52.04) v1(126.75,57.12) v1(126.93,76.42) v1(127.04,80.22) v1(127.03,78.4) v1(127.14,70.35) v1(127.14,68.7) v1(127.14,65.78) v1(127.14,62.73) v1(127.23,83.29) v1(127.19,82.05) v1(127.16,67.25) v1(127.16,64.33) v1(127.16,61.28) v1(127.24,59.78) v1(127.19,13.35) v1(127.31,72.05) v1(127.29,54.96) v1(127.29,53.64) v1(127.38,43.91) v1(127.49,11.86) v1(127.52,10.41) v1(127.64,74.26) v1(127.59,9.19) v1(127.8,46.25) v1(128.29,67.12) v1(128.37,65.19) v1(128.5,82.21) v1(128.52,58.77) v1(128.52,48.53) v1(128.65,83.31) v1(128.71,76.43) v1(128.71,75.16) v1(128.71,73.89) v1(128.71,72.62) v1(128.71,71.35) v1(128.71,45.15) v1(128.68,27.98) v1(128.74,11.86) v1(128.81,63.68) v1(128.84,59.73) v1(128.81,55.59) v1(128.89,61.52) v1(128.89,51.63) v1(128.94,49.65) v1(128.91,41.22) v1(128.91,37.41) v1(128.93,34.99) v1(128.94,30.55) v1(128.97,80.14) v1(128.96,78.33) v1(128.99,25.11) v1(129.07,53.46) v1(129.08,32.91) v1(129.17,10.41) v1(129.24,9.19) v1(129.27,19.09) v1(129.4,21.25) v1(129.57,72.99) v1(129.57,71.72) v1(129.57,70.45) v1(129.57,69.18) v1(129.6,67.92) v1(129.6,66.65) v1(129.6,65.38) v1(129.57,26.94) v1(129.82,82.19) v1(129.83,17.27) v1(129.87,83.43) v1(129.9,23.11) v1(129.98,29.48) v1(130.1,35.76) v1(130.18,46.93) v1(130.23,41.29) v1(130.23,37.79) v1(130.21,10.36) v1(130.33,64.1) v1(130.33,62.83) v1(130.33,60.29) v1(130.41,53.99) v1(130.38,33.55) v1(130.4,31.62) v1(130.54,51.94) v1(130.51,9.19) v1(130.74,80.87) v1(130.74,79.6) v1(130.75,78.47) v1(130.84,72.99) v1(130.84,71.72) v1(130.84,70.45) v1(130.84,69.18) v1(130.84,66.64) v1(130.84,65.37) v1(130.84,61.56) v1(130.92,19.09) v1(131.02,49.5) v1(131.02,28.42) v1(131.35,82.21) v1(131.25,47.19) v1(131.25,42.79) v1(131.43,16.02) v1(131.47,83.43) v1(131.48,17.27) v1(131.6,68.17) v1(131.68,53.38) v1(131.66,52.27) v1(131.75,36.06) v1(131.75,34.13) v1(131.75,32.18) v1(131.78,64.89) v1(131.76,63.62) v1(131.76,62.35) v1(131.78,61.05) v1(131.78,59.92) v1(131.78,58.65) v1(131.76,55.44) v1(131.81,50.62) v1(131.78,37.61) v1(131.78,30.24) v1(131.76,9.01) v1(132.01,80.87) v1(132.01,79.6) v1(132.01,78.33) v1(132.11,76.42) v1(132.11,75.15) v1(132.11,73.25) v1(132.11,71.34) v1(132.11,70.07) v1(132.11,66.26) v1(132.14,27.65) v1(132.19,19.09) v1(132.57,47.14) v1(132.57,43.73) v1(132.75,17.27) v1(132.95,63.59) v1(132.95,62.32) v1(132.95,61.05) v1(132.95,59.78) v1(132.95,58.51) v1(132.95,57.24) v1(132.85,14.8) v1(132.99,83.46) v1(132.95,53.05) v1(132.95,49.53) v1(133.03,9.01) v1(133.1,38.75) v1(133.1,29.03) v1(133.08,16.02) v1(133.16,51.07) v1(133.17,30.73) v1(133.28,82.14) v1(133.32,80.71) v1(133.28,79.6) v1(133.28,78.33) v1(133.25,68.29) v1(133.31,66.38) v1(133.38,77.06) v1(133.38,75.79) v1(133.38,73.88) v1(133.38,71.98) v1(133.38,69.44) v1(133.6,34.21) v1(133.74,13.86) v1(134.01,76.42) v1(134.01,75.15) v1(134.01,73.25) v1(134.01,71.34) v1(134.01,70.07) v1(134.14,65.5) v1(134.07,47.91) v1(134.17,18.76) v1(134.35,16.02) v1(134.3,9.01) v1(134.37,17.6) v1(134.49,83.46) v1(134.52,63.59) v1(134.52,62.32) v1(134.52,61.05) v1(134.52,59.78) v1(134.52,58.51) v1(134.52,57.24) v1(134.5,55.49) v1(134.53,53.87) v1(134.53,52.42) v1(134.45,49.78) v1(134.55,79.99) v1(134.65,78.33) v1(134.65,77.44) v1(134.58,67.65) v1(135.03,79.01) v1(135.03,76.68) v1(135.03,70.96) v1(135.01,13.86) v1(135.09,66.45) v1(135.18,51.16) v1(135.25,48.91) v1(135.41,69.82) v1(135.36,31.72) v1(135.39,30.37) v1(135.47,29.03) v1(135.47,27.68) v1(135.57,79.86) v1(135.57,9.01) v1(135.66,76.22) v1(135.66,75.02) v1(135.66,74.01) v1(135.66,72.99) v1(135.66,71.85) v1(135.85,68.92) v1(135.92,64.99) v1(136.02,83.48) v1(136.04,79.22) v1(136.04,62.32) v1(136.04,61.05) v1(136.04,59.78) v1(136.04,58.51) v1(136.04,57.24) v1(136.04,55.28) v1(136,52.88) v1(136.17,71.21) v1(136.28,13.86) v1(136.36,67.72) v1(136.47,49.85) v1(136.53,46.96) v1(136.61,42.21) v1(136.56,18.05) v1(136.76,40.58) v1(136.84,9.01) v1(136.93,63.34) v1(137.12,45.81) v1(137.09,45.05) v1(137.19,79.22) v1(137.19,71.21) v1(137.19,70.33) v1(137.19,60.8) v1(137.3,17.8) v1(137.44,76.17) v1(137.44,75.15) v1(137.44,74.01) v1(137.43,53.68) v1(137.55,57.32) v1(137.55,56.43) v1(137.47,55.22) v1(137.47,51) v1(137.59,83.43) v1(137.57,73.12) v1(137.57,30.37) v1(137.75,46.39) v1(137.95,79.72) v1(137.95,78.83) v1(137.95,71.21) v1(138.08,68.67) v1(138.05,66.26) v1(138.11,58.15) v1(138.13,40.66) v1(138.11,9.01) v1(138.2,64.1) v1(138.2,61.82) v1(138.24,58.91) v1(138.18,48.18) v1(138.18,42.21) v1(138.36,55.06) v1(138.36,45.1) v1(138.49,29.15) v1(138.58,76.68) v1(138.58,75.79) v1(138.58,74.77) v1(138.71,70.33) v1(138.84,71.21) v1(138.84,52.68) v1(139.12,83.46) v1(139.13,80.24) v1(139.09,58.03) v1(139.07,54.2) v1(139.42,46.92) v1(139.38,9.01) v1(139.48,58.85) v1(139.53,51.05) v1(139.48,27.86) v1(139.68,82.24) v1(139.73,74.77) v1(139.67,71.21) v1(139.93,78.25) v1(139.93,77.49) v1(139.85,76.68) v1(139.85,75.79) v1(139.9,38.76) v1(139.9,37.44) v1(139.99,45.05) v1(139.99,43.3) v1(140.01,41.9) v1(139.96,30.57) v1(140.11,54.2) v1(140.17,70.58) v1(140.18,55.09) v1(140.29,80.23) v1(140.44,81.25) v1(140.42,52.83) v1(140.37,48.1) v1(140.39,29.08) v1(140.52,82.29) v1(140.64,83.41) v1(140.65,71.21) v1(140.62,58.13) v1(140.95,14.78) v1(140.95,13.81) v1(141.12,58.87) v1(141.08,51.2) v1(141.2,38.76) v1(141.17,37.44) v1(141.17,36.17) v1(141.18,8.98) v1(141.38,54.2) v1(141.48,71.21) v1(141.49,42.84) v1(141.63,58.13) v1(141.61,30.14) v1(141.74,52.8) v1(141.74,46.27) v1(141.96,70.57) v1(142.04,55.09) v1(142.16,83.43) v1(142.35,48.13) v1(142.44,38.76) v1(142.44,37.44) v1(142.44,36.17) v1(142.45,8.98) v1(142.65,80.49) v1(142.65,79.6) v1(142.65,78.25) v1(142.65,77.44) v1(142.65,76.17) v1(142.65,74.9) v1(142.65,54.2) v1(142.6,51.23) v1(142.73,59.43) v1(142.65,44.8) v1(142.78,58.13) v1(143.26,52.83) v1(143.41,61.31) v1(143.44,25.52) v1(143.54,73.88) v1(143.49,17.8) v1(143.54,14.78) v1(143.6,73.03) v1(143.62,19.37) v1(143.57,16.07) v1(143.59,13.66) v1(143.74,75.53) v1(143.72,46.81) v1(143.72,24.02) v1(143.72,20.77) v1(143.72,8.98) v1(143.76,83.43) v1(143.79,71.98) v1(143.79,59.66) v1(143.79,58.13) v1(143.84,55.09) v1(143.8,48.13) v1(143.85,42.03) v1(143.92,54.2) v1(144.03,22.35) v1(144.21,51.23) v1(144.25,74.77) v1(144.54,80.35) v1(144.55,81.37) v1(144.63,77.44) v1(144.69,25.14) v1(144.81,56.36) v1(144.81,55.09) v1(144.76,27.07) v1(144.76,17.8) v1(144.84,16.07) v1(144.81,14.78) v1(144.84,13.33) v1(144.92,75.54) v1(144.94,43.35) v1(144.89,19.37) v1(144.99,20.77) v1(144.99,8.98) v1(145.06,82.06) v1(145.09,52.83) v1(145.19,54.2) v1(145.17,42.36) v1(145.29,83.46) v1(145.27,80.62) v1(145.32,47.95) v1(145.39,77.95) v1(145.39,74.77) v1(145.44,60.7) v1(145.44,59.66) v1(145.48,78.87) v1(145.53,73.94) v1(145.49,40.74) v1(145.57,67.28) v1(145.57,66.52) v1(145.57,65.75) v1(145.7,81.5) v1(145.65,32.18) v1(145.78,75.57) v1(145.83,72.95) v1(145.82,58.13) v1(145.9,72) v1(145.87,70.66) v1(145.92,56.36) v1(145.88,45.28) v1(146.03,17.8) v1(146.14,51.26) v1(146.11,28.34) v1(146.11,16.07) v1(146.08,14.78) v1(146.11,13.33) v1(146.16,82.26) v1(146.16,19.37) v1(146.33,60.72) v1(146.33,59.66) v1(146.26,43.33) v1(146.26,20.77) v1(146.26,8.98) v1(146.36,67.29) v1(146.36,66.53) v1(146.36,65.76) v1(146.41,52.8) v1(146.46,55.21) v1(146.46,54.2) v1(146.72,38.37) v1(146.8,81.64) v1(146.99,83.43) v1(147.12,67.29) v1(147.12,66.53) v1(147.12,65.76) v1(147.2,45.26) v1(147.3,46.78) v1(147.3,17.8) v1(147.43,78.71) v1(147.43,77.69) v1(147.43,76.68) v1(147.43,19.37) v1(147.38,16.07) v1(147.35,14.78) v1(147.38,13.33) v1(147.48,82.15) v1(147.53,20.77) v1(147.53,8.98) v1(147.6,75.91) v1(147.6,74.9) v1(147.6,74.14) v1(147.63,71.57) v1(147.6,70.45) v1(147.73,60.75) v1(147.73,59.66) v1(147.79,43.35) v1(147.94,52.83) v1(147.99,51.87) v1(148.24,54.65) v1(148.45,82.24) v1(148.36,76.29) v1(148.36,74.14) v1(148.51,83.46) v1(148.49,75.15) v1(148.49,57.88) v1(148.62,46.75) v1(148.65,22.32) v1(148.7,78.83) v1(148.7,77.82) v1(148.73,45.28) v1(148.8,8.98) v1(148.87,60.75) v1(148.87,59.66) v1(149.13,76.68) v1(149.13,74.14) v1(149.13,42.36) v1(149.23,51.07) v1(149.36,43.38) v1(149.51,57.88) v1(149.49,52.95) v1(149.63,75.15) v1(149.63,71.6) v1(149.63,70.58) v1(149.64,48.03) v1(149.71,77.82) v1(149.89,74.14) v1(149.92,44.52) v1(149.89,38.3) v1(149.92,36.85) v1(149.92,35.35) v1(149.94,33.7) v1(150.01,76.68) v1(150.01,61.69) v1(150.01,60.8) v1(150.01,59.66) v1(150.02,10.38) v1(150.14,54.63) v1(150.15,46.78) v1(150.07,8.98) v1(150.19,83.43) v1(150.25,78.76) v1(150.4,72.1) v1(150.43,51.79) v1(150.52,57.88) v1(150.47,48.12) v1(150.5,13.35) v1(150.65,76.17) v1(150.65,75.28) v1(150.65,74.14) v1(150.63,41.5) v1(150.78,70.58) v1(150.81,52.93) v1(150.81,39.13) v1(151.03,61.69) v1(151.03,60.8) v1(151.03,59.66) v1(151.21,51) v1(151.27,48.16) v1(151.27,10.69) v1(151.34,8.98) v1(151.54,57.88) v1(151.61,63.01) v1(151.64,54.65) v1(151.71,83.46) v1(151.87,70.58) v1(152.05,61.69) v1(152.05,60.8) v1(152.05,59.53) v1(152.03,40.15) v1(152.11,48.16) v1(152.32,64.87) v1(152.27,63.47) v1(152.33,52.95) v1(152.28,51.81) v1(152.43,76.17) v1(152.43,75.15) v1(152.46,74.27) v1(152.51,73.5) v1(152.51,72.61) v1(152.54,10.69) v1(152.61,8.98) v1(152.68,59.1) v1(152.68,54.2) v1(152.74,25.27) v1(152.86,78.81) v1(152.86,47.89) v1(152.91,33.57) v1(153.01,70.58) v1(153.04,58.24) v1(153.04,46.35) v1(153.07,47.13) v1(153.07,44.9) v1(153.07,43.4) v1(153.09,41.75) v1(153.12,40.07) v1(153.14,38.63) v1(153.14,37.13) v1(153.13,36.07) v1(153.19,68.17) v1(153.31,83.43) v1(153.27,76.55) v1(153.28,35.19) v1(153.44,54.93) v1(153.53,57.59) v1(153.52,56.74) v1(153.51,55.88) v1(153.45,34.23) v1(153.6,78.47) v1(153.57,77.44) v1(153.59,13.28) v1(153.7,67.02) v1(153.7,65.5) v1(153.7,64.23) v1(153.7,63.21) v1(153.7,62.07) v1(153.78,70.62) v1(153.78,61.05) v1(153.83,25.24) v1(153.81,10.69) v1(153.88,8.98) v1(154.03,69.56) v1(154.41,60.42) v1(154.35,51.8) v1(154.54,76.68) v1(154.64,26.03) v1(154.75,17.75) v1(154.66,16.79) v1(154.84,83.46) v1(154.78,82.2) v1(154.97,78.83) v1(154.97,77.69) v1(155.11,80.86) v1(155.08,67.16) v1(155.13,65.77) v1(155.09,64.99) v1(155.09,63.98) v1(155.09,62.96) v1(155.09,61.82) v1(155.08,10.69) v1(155.17,69.69) v1(155.2,59.58) v1(155.22,54.2) v1(155.15,8.98) v1(155.3,68.93) v1(155.28,49.88) v1(155.53,53.1) v1(155.6,58.29) v1(155.62,57.24) v1(155.68,76.55) v1(155.73,56.1) v1(155.73,13.3) v1(155.79,82.2) v1(155.76,34.08) v1(155.89,19.55) v1(156.02,65.26) v1(156.24,80.87) v1(156.24,78.83) v1(156.24,77.69) v1(156.19,28.34) v1(156.27,27.43) v1(156.35,10.69) v1(156.39,83.28) v1(156.4,55.35) v1(156.41,49.42) v1(156.42,8.98) v1(156.48,51.83) v1(156.52,48.28) v1(156.7,73.63) v1(156.7,72.36) v1(156.7,71.47) v1(156.7,54.2) v1(156.83,41.83) v1(156.87,64.23) v1(156.87,63.21) v1(156.87,62.07) v1(156.87,61.05) v1(156.87,60.04) v1(156.91,59.16) v1(157.21,65.5) v1(157.33,78.45) v1(157.35,18.24) v1(157.36,19.07) v1(157.47,82.09) v1(157.51,80.87) v1(157.51,13.33) v1(157.56,22.8) v1(157.56,21.46) v1(157.56,20.39) v1(157.62,10.69) v1(157.71,72.74) v1(157.69,54.54) v1(157.67,9.16) v1(157.84,71.47) v1(157.91,83.31) v1(157.91,53) v1(158.02,65.02) v1(158.14,61.97) v1(158.22,63.77) v1(158.2,60.37) v1(158.3,41.88) v1(158.6,80.87) v1(158.58,22.8) v1(158.61,21.46) v1(158.61,20.34) v1(158.74,82.09) v1(158.73,73.75) v1(158.92,79.85) v1(158.86,72.61) v1(158.86,71.47) v1(158.86,70.33) v1(158.88,52.74) v1(158.89,10.69) v1(158.94,9.16) v1(158.98,69.31) v1(158.98,55.44) v1(158.99,51.61) v1(159.1,68.53) v1(159.11,67.53) v1(159.09,42.94) v1(159.05,11.78) v1(159.19,58.02) v1(159.25,56.52) v1(159.36,64.99) v1(159.36,63.47) v1(159.45,54.51) v1(159.49,61.79) v1(159.49,60.52) v1(159.49,59.25) v1(159.56,79.22) v1(159.65,41.9) v1(159.79,83.28) v1(159.83,82.09) v1(160.1,43.78) v1(160.21,22.78) v1(160.21,21.46) v1(160.21,20.34) v1(160.16,10.69) v1(160.21,9.16) v1(160.3,47.94) v1(160.44,80.88) v1(160.41,80.03) v1(160.43,63.52) v1(160.41,46.81) v1(160.64,65.13) v1(160.63,56.04) v1(160.74,61.98) v1(160.74,54.91) v1(160.68,13.18) v1(160.68,11.83) v1(160.76,78.45) v1(160.76,77.18) v1(160.76,75.91) v1(160.76,74.64) v1(160.76,73.37) v1(160.76,72.1) v1(160.76,70.83) v1(160.96,52.84) v1(160.97,43.76) v1(161.07,51.71) v1(161.32,83.31) v1(161.31,68.51) v1(161.41,69.91) v1(161.48,9.16) v1(161.67,82.11) v1(161.83,75.47) v1(161.76,67.47) v1(161.81,48.08) v1(161.81,22.78) v1(161.81,21.48) v1(161.78,20.29) v1(161.88,73.16) v1(162.04,65.13) v1(162.14,61.98) v1(162.35,74.1) v1(162.37,68.66) v1(162.38,56.04) v1(162.49,54.91) v1(162.69,83.25) v1(163.08,69.86) v1(163.15,67.47) v1(163.3,29.53) v1(163.56,65.13) v1(163.76,68.66) v1(164.12,69.89) v1(164.19,67.51) v1(164.32,29.43) v1(164.34,21.2) v1(164.41,75.02) v1(164.4,39.57) v1(164.55,35.96) v1(164.57,37.28) v1(164.57,33.5) v1(164.8,68.7) v1(164.93,31.46) v1(165.05,73.73) v1(164.96,65.13) v1(165.16,34.77) v1(165.34,27.68) v1(165.36,28.75) v1(165.46,22.88) v1(165.67,26.33) v1(165.79,30.07) v1(165.87,69.65) v1(166.05,73.03) v1(165.96,55.82) v1(166.13,67.19) v1(166.07,54.68) v1(166.07,46.12) v1(166.18,31.44) v1(166.28,17.49) v1(166.37,74.92) v1(166.58,63.9) v1(166.68,25.37) v1(166.66,24.43) v1(166.71,23.21) v1(166.89,68.33) v1(166.96,37.28) v1(166.99,34.72) v1(167.09,71.2) v1(167.09,65.99) v1(167.11,56.1) v1(167.11,54.83) v1(167.11,53.56) v1(167.11,52.29) v1(167.11,51.02) v1(167.11,49.75) v1(167.11,48.48) v1(167.11,47.21) v1(167.09,35.93) v1(167.19,27.48) v1(167.19,22.12) v1(167.27,69.65) v1(167.29,31.44) v1(167.27,29.94) v1(167.45,73.03) v1(167.52,67.19) v1(167.83,62.68) v1(167.93,68.37) v1(168.07,83.31) v1(168.13,71.24) v1(168.08,19.07) v1(168.16,17.54) v1(168.31,69.69) v1(168.44,64.51) v1(168.38,16.58) v1(168.35,9.34) v1(168.49,73.07) v1(168.49,65.99) v1(168.64,74.87) v1(168.56,67.23) v1(169.16,82.34) v1(169.44,77.46) v1(169.35,75.94) v1(169.43,74.14) v1(169.43,72.87) v1(169.43,71.6) v1(169.43,70.33) v1(169.43,69.06) v1(169.43,67.79) v1(169.43,66.52) v1(169.43,65.25) v1(169.43,63.98) v1(169.43,62.71) v1(169.43,61.44) v1(169.43,60.17) v1(169.43,58.9) v1(169.43,57.63) v1(169.43,56.36) v1(169.43,55.09) v1(169.43,53.82) v1(169.43,52.55) v1(169.43,51.28) v1(169.43,50.01) v1(169.43,48.74) v1(169.43,47.47) v1(169.43,46.2) v1(169.43,44.93) v1(169.43,43.66) v1(169.43,42.39) v1(169.43,41.12) v1(169.43,39.85) v1(169.43,38.58) v1(169.43,37.31) v1(169.43,36.04) v1(169.43,34.77) v1(169.43,32.23) v1(169.43,30.96) v1(169.43,29.69) v1(169.43,28.42) v1(169.43,27.15) v1(169.43,25.88) v1(169.43,24.61) v1(169.43,23.34) v1(169.43,22.07) v1(169.43,20.8) v1(169.43,15.72) v1(169.48,33.5) v1(169.45,19.12) v1(169.48,17.52) v1(169.49,10.89)
